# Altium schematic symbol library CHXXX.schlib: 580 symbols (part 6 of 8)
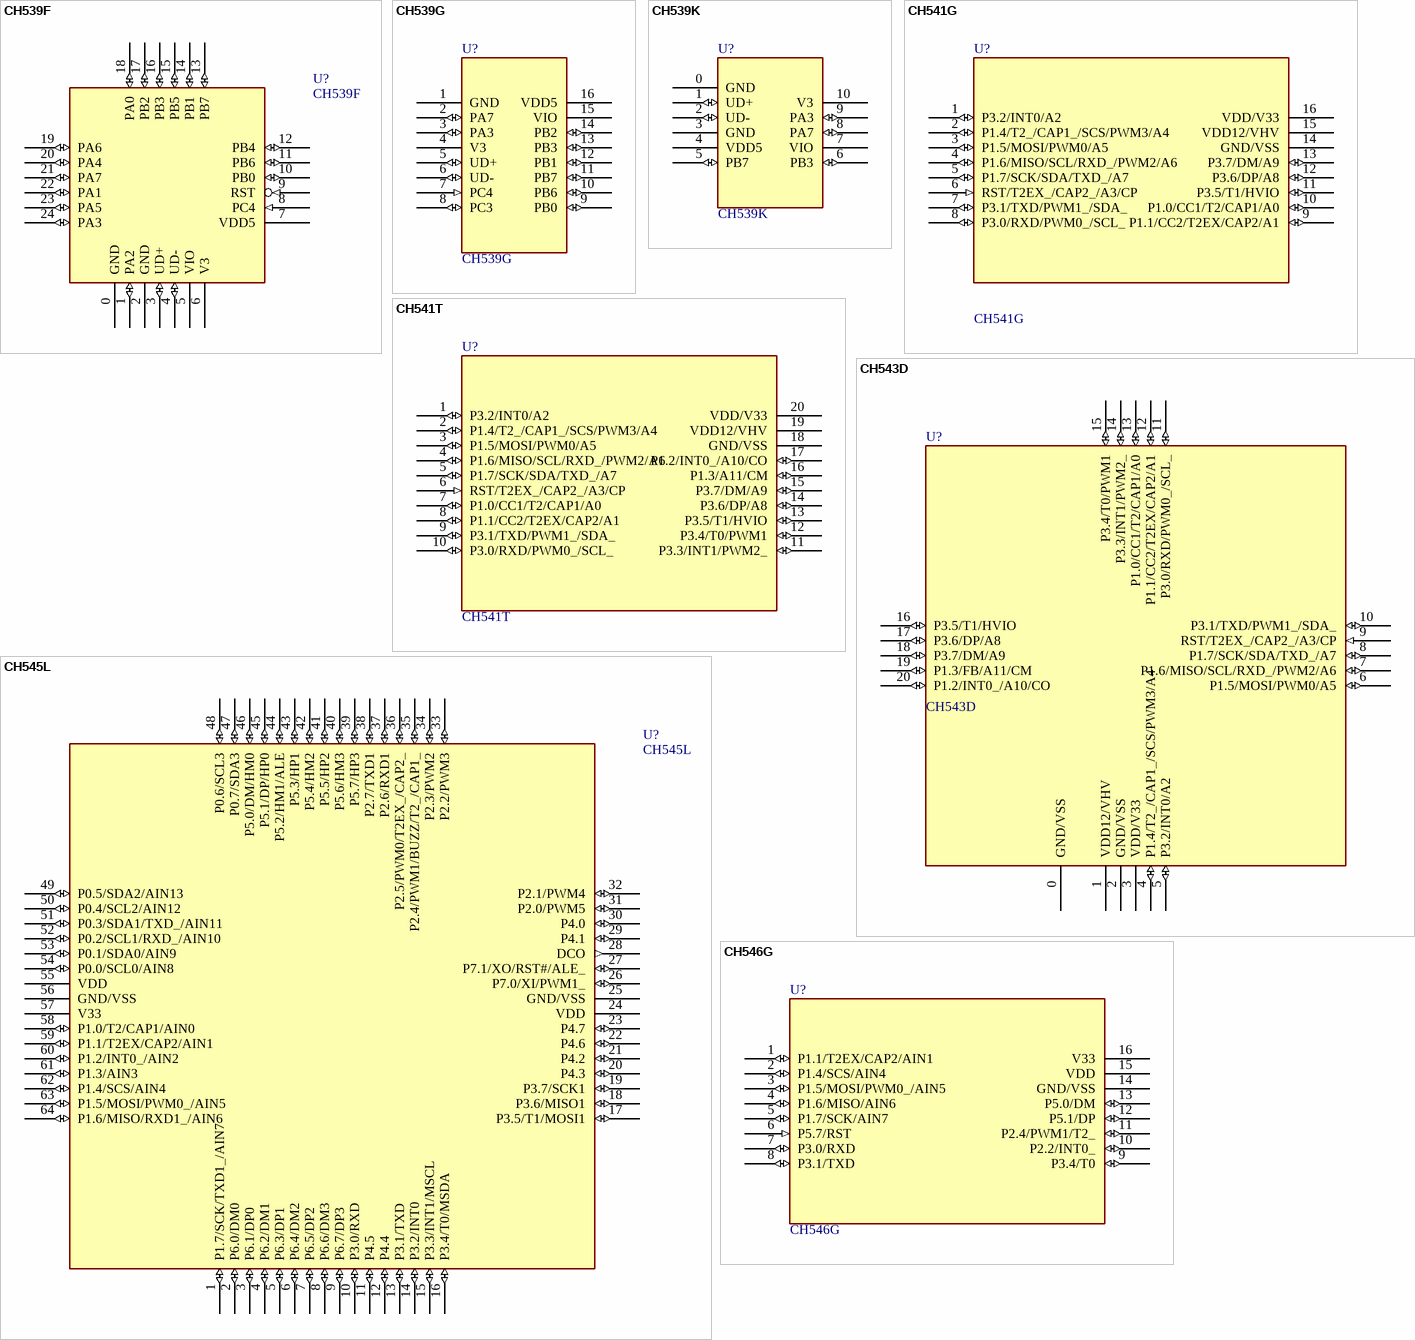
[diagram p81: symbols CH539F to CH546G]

## CH546G
designator U?
8bit MCS51 MCU with ADC & USB device & UART & SPI
footprint SOP16
footprint DIP16
pins: 1 P1.1/T2EX/CAP2/AIN1 (io), 2 P1.4/SCS/AIN4 (io), 3 P1.5/MOSI/PWM0_/AIN5 (io), 4 P1.6/MISO/AIN6 (io), 5 P1.7/SCK/AIN7 (io), 6 P5.7/RST (in), 7 P3.0/RXD (io), 8 P3.1/TXD (io), 9 P3.4/T0 (io), 10 P2.2/INT0_ (io), 11 P2.4/PWM1/T2_ (io), 12 P5.1/DP (io), 13 P5.0/DM (io), 14 GND/VSS (power), 15 VDD (power), 16 V33 (power)

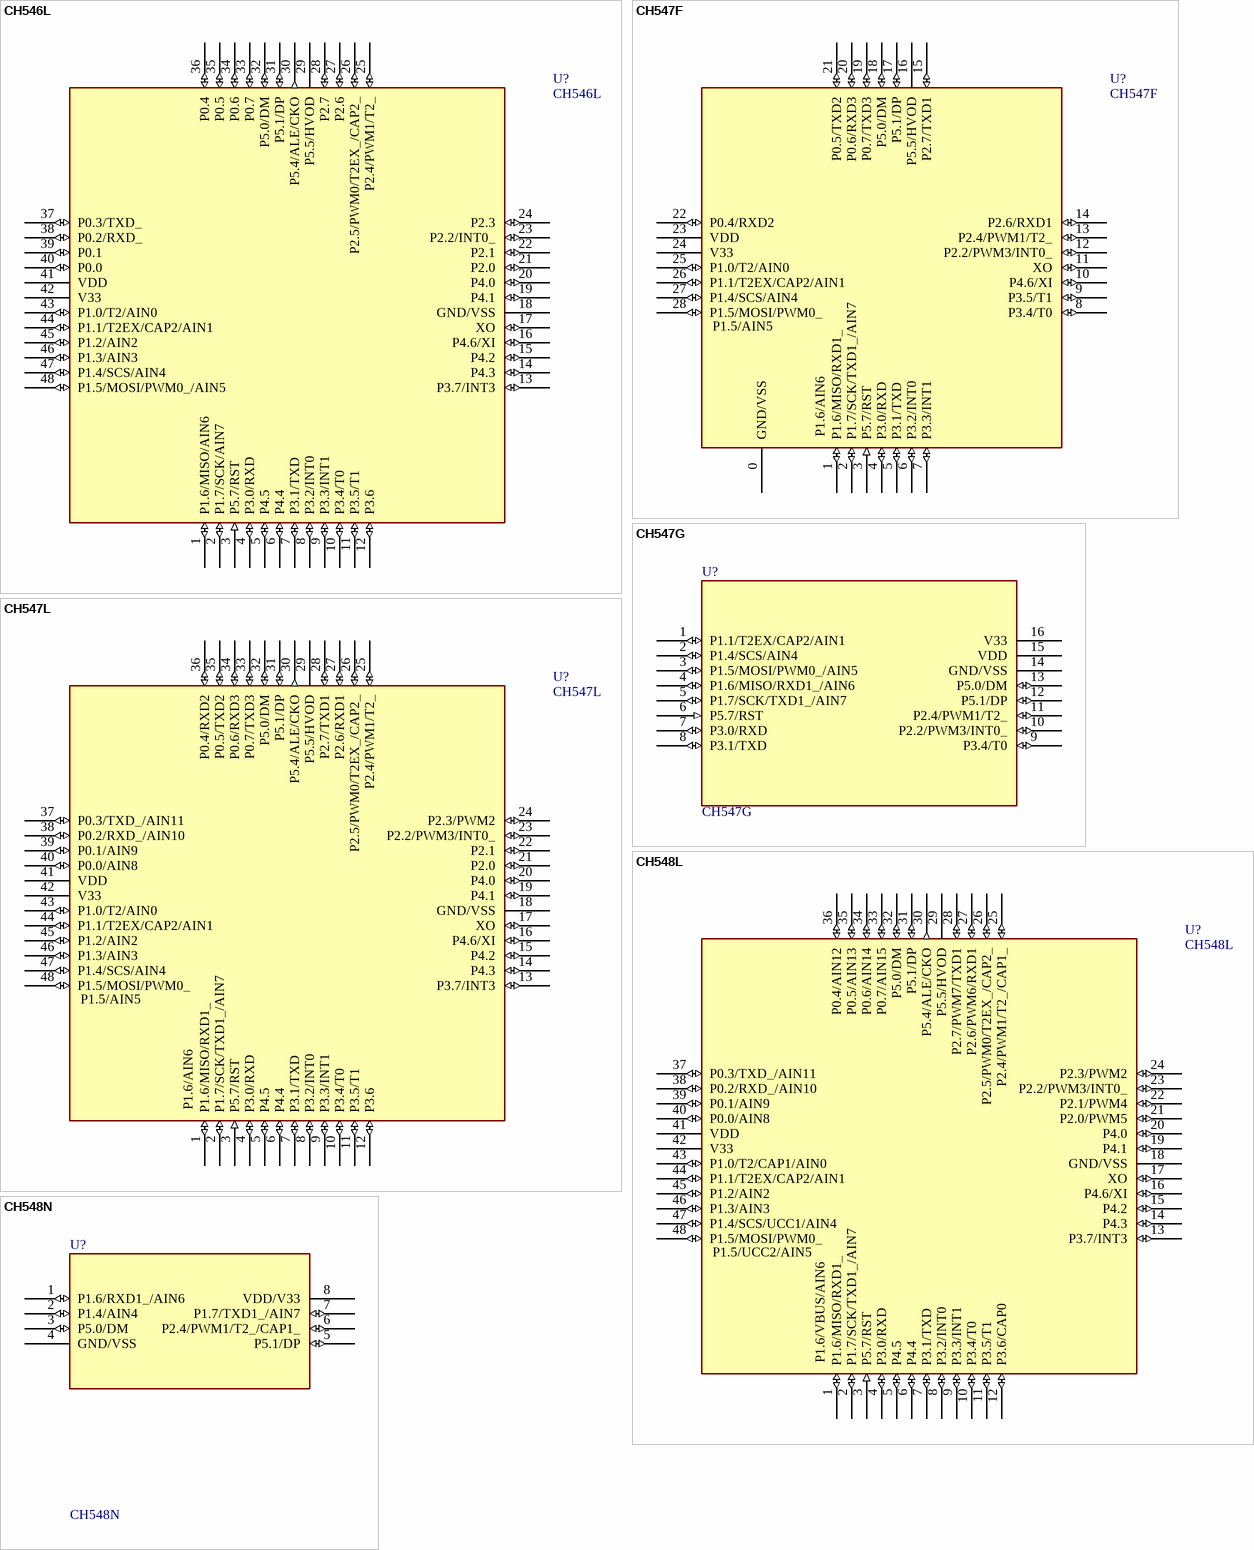
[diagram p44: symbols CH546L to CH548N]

## CH546L
designator U?
8bit MCS51 MCU with ADC & USB device & UART & SPI
footprint LQFP48
pins: 1 P1.6/MISO/AIN6 (io), 2 P1.7/SCK/AIN7 (io), 3 P5.7/RST (in), 4 P3.0/RXD (io), 5 P4.5 (io), 6 P4.4 (io), 7 P3.1/TXD (io), 8 P3.2/INT0 (io), 9 P3.3/INT1 (io), 10 P3.4/T0 (io), 11 P3.5/T1 (io), 12 P3.6 (io), 13 P3.7/INT3 (io), 14 P4.3 (io), 15 P4.2 (io), 16 P4.6/XI (io), 17 XO (io), 18 GND/VSS (power), 19 P4.1 (io), 20 P4.0 (io), 21 P2.0 (io), 22 P2.1 (io), 23 P2.2/INT0_ (io), 24 P2.3 (io), 25 P2.4/PWM1/T2_ (io), 26 P2.5/PWM0/T2EX_/CAP2_ (io), 27 P2.6 (io), 28 P2.7 (io), 29 P5.5/HVOD (oc), 30 P5.4/ALE/CKO (out), 31 P5.1/DP (io), 32 P5.0/DM (io), 33 P0.7 (io), 34 P0.6 (io), 35 P0.5 (io), 36 P0.4 (io), 37 P0.3/TXD_ (io), 38 P0.2/RXD_ (io), 39 P0.1 (io), 40 P0.0 (io), 41 VDD (power), 42 V33 (power), 43 P1.0/T2/AIN0 (io), 44 P1.1/T2EX/CAP2/AIN1 (io), 45 P1.2/AIN2 (io), 46 P1.3/AIN3 (io), 47 P1.4/SCS/AIN4 (io), 48 P1.5/MOSI/PWM0_/AIN5 (io)

## CH547F
designator U?
8bit MCS51 MCU with ADC & USB device & quad UART & SPI
footprint QFN28_4X4
pins: 0 GND/VSS (power), 1 P1.6/MISO/RXD1_ (io), 2 P1.7/SCK/TXD1_/AIN7 (io), 3 P5.7/RST (in), 4 P3.0/RXD (io), 5 P3.1/TXD (io), 6 P3.2/INT0 (io), 7 P3.3/INT1 (io), 8 P3.4/T0 (io), 9 P3.5/T1 (io), 10 P4.6/XI (io), 11 XO (io), 12 P2.2/PWM3/INT0_ (io), 13 P2.4/PWM1/T2_ (io), 14 P2.6/RXD1 (io), 15 P2.7/TXD1 (io), 16 P5.5/HVOD (oc), 17 P5.1/DP (io), 18 P5.0/DM (io), 19 P0.7/TXD3 (io), 20 P0.6/RXD3 (io), 21 P0.5/TXD2 (io), 22 P0.4/RXD2 (io), 23 VDD (power), 24 V33 (power), 25 P1.0/T2/AIN0 (io), 26 P1.1/T2EX/CAP2/AIN1 (io), 27 P1.4/SCS/AIN4 (io), 28 P1.5/MOSI/PWM0_ (io)

## CH547G
designator U?
8bit MCS51 MCU with ADC & USB device & dual UART & SPI
footprint SOP16
footprint DIP16
pins: 1 P1.1/T2EX/CAP2/AIN1 (io), 2 P1.4/SCS/AIN4 (io), 3 P1.5/MOSI/PWM0_/AIN5 (io), 4 P1.6/MISO/RXD1_/AIN6 (io), 5 P1.7/SCK/TXD1_/AIN7 (io), 6 P5.7/RST (in), 7 P3.0/RXD (io), 8 P3.1/TXD (io), 9 P3.4/T0 (io), 10 P2.2/PWM3/INT0_ (io), 11 P2.4/PWM1/T2_ (io), 12 P5.1/DP (io), 13 P5.0/DM (io), 14 GND/VSS (power), 15 VDD (power), 16 V33 (power)

## CH547L
designator U?
8bit MCS51 MCU with ADC & USB device & quad UART & SPI
footprint LQFP48
pins: 1 P1.6/MISO/RXD1_ (io), 2 P1.7/SCK/TXD1_/AIN7 (io), 3 P5.7/RST (in), 4 P3.0/RXD (io), 5 P4.5 (io), 6 P4.4 (io), 7 P3.1/TXD (io), 8 P3.2/INT0 (io), 9 P3.3/INT1 (io), 10 P3.4/T0 (io), 11 P3.5/T1 (io), 12 P3.6 (io), 13 P3.7/INT3 (io), 14 P4.3 (io), 15 P4.2 (io), 16 P4.6/XI (io), 17 XO (io), 18 GND/VSS (power), 19 P4.1 (io), 20 P4.0 (io), 21 P2.0 (io), 22 P2.1 (io), 23 P2.2/PWM3/INT0_ (io), 24 P2.3/PWM2 (io), 25 P2.4/PWM1/T2_ (io), 26 P2.5/PWM0/T2EX_/CAP2_ (io), 27 P2.6/RXD1 (io), 28 P2.7/TXD1 (io), 29 P5.5/HVOD (oc), 30 P5.4/ALE/CKO (out), 31 P5.1/DP (io), 32 P5.0/DM (io), 33 P0.7/TXD3 (io), 34 P0.6/RXD3 (io), 35 P0.5/TXD2 (io), 36 P0.4/RXD2 (io), 37 P0.3/TXD_/AIN11 (io), 38 P0.2/RXD_/AIN10 (io), 39 P0.1/AIN9 (io), 40 P0.0/AIN8 (io), 41 VDD (power), 42 V33 (power), 43 P1.0/T2/AIN0 (io), 44 P1.1/T2EX/CAP2/AIN1 (io), 45 P1.2/AIN2 (io), 46 P1.3/AIN3 (io), 47 P1.4/SCS/AIN4 (io), 48 P1.5/MOSI/PWM0_ (io)

## CH548L
designator U?
8bit MCS51 MCU with ADC & USB type-C host & device & double UART & SPI
footprint LQFP48
pins: 1 P1.6/MISO/RXD1_ (io), 2 P1.7/SCK/TXD1_/AIN7 (io), 3 P5.7/RST (in), 4 P3.0/RXD (io), 5 P4.5 (io), 6 P4.4 (io), 7 P3.1/TXD (io), 8 P3.2/INT0 (io), 9 P3.3/INT1 (io), 10 P3.4/T0 (io), 11 P3.5/T1 (io), 12 P3.6/CAP0 (io), 13 P3.7/INT3 (io), 14 P4.3 (io), 15 P4.2 (io), 16 P4.6/XI (io), 17 XO (io), 18 GND/VSS (power), 19 P4.1 (io), 20 P4.0 (io), 21 P2.0/PWM5 (io), 22 P2.1/PWM4 (io), 23 P2.2/PWM3/INT0_ (io), 24 P2.3/PWM2 (io), 25 P2.4/PWM1/T2_/CAP1_ (io), 26 P2.5/PWM0/T2EX_/CAP2_ (io), 27 P2.6/PWM6/RXD1 (io), 28 P2.7/PWM7/TXD1 (io), 29 P5.5/HVOD (oc), 30 P5.4/ALE/CKO (out), 31 P5.1/DP (io), 32 P5.0/DM (io), 33 P0.7/AIN15 (io), 34 P0.6/AIN14 (io), 35 P0.5/AIN13 (io), 36 P0.4/AIN12 (io), 37 P0.3/TXD_/AIN11 (io), 38 P0.2/RXD_/AIN10 (io), 39 P0.1/AIN9 (io), 40 P0.0/AIN8 (io), 41 VDD (power), 42 V33 (power), 43 P1.0/T2/CAP1/AIN0 (io), 44 P1.1/T2EX/CAP2/AIN1 (io), 45 P1.2/AIN2 (io), 46 P1.3/AIN3 (io), 47 P1.4/SCS/UCC1/AIN4 (io), 48 P1.5/MOSI/PWM0_ (io)

## CH548N
designator U?
8bit MCS51 MCU with ADC & USB host & device & UART
footprint SOP8 (Footprint not found)
pins: 1 P1.6/RXD1_/AIN6 (io), 2 P1.4/AIN4 (io), 3 P5.0/DM (io), 4 GND/VSS (power), 5 P5.1/DP (io), 6 P2.4/PWM1/T2_/CAP1_ (io), 7 P1.7/TXD1_/AIN7 (io), 8 VDD/V33 (power)

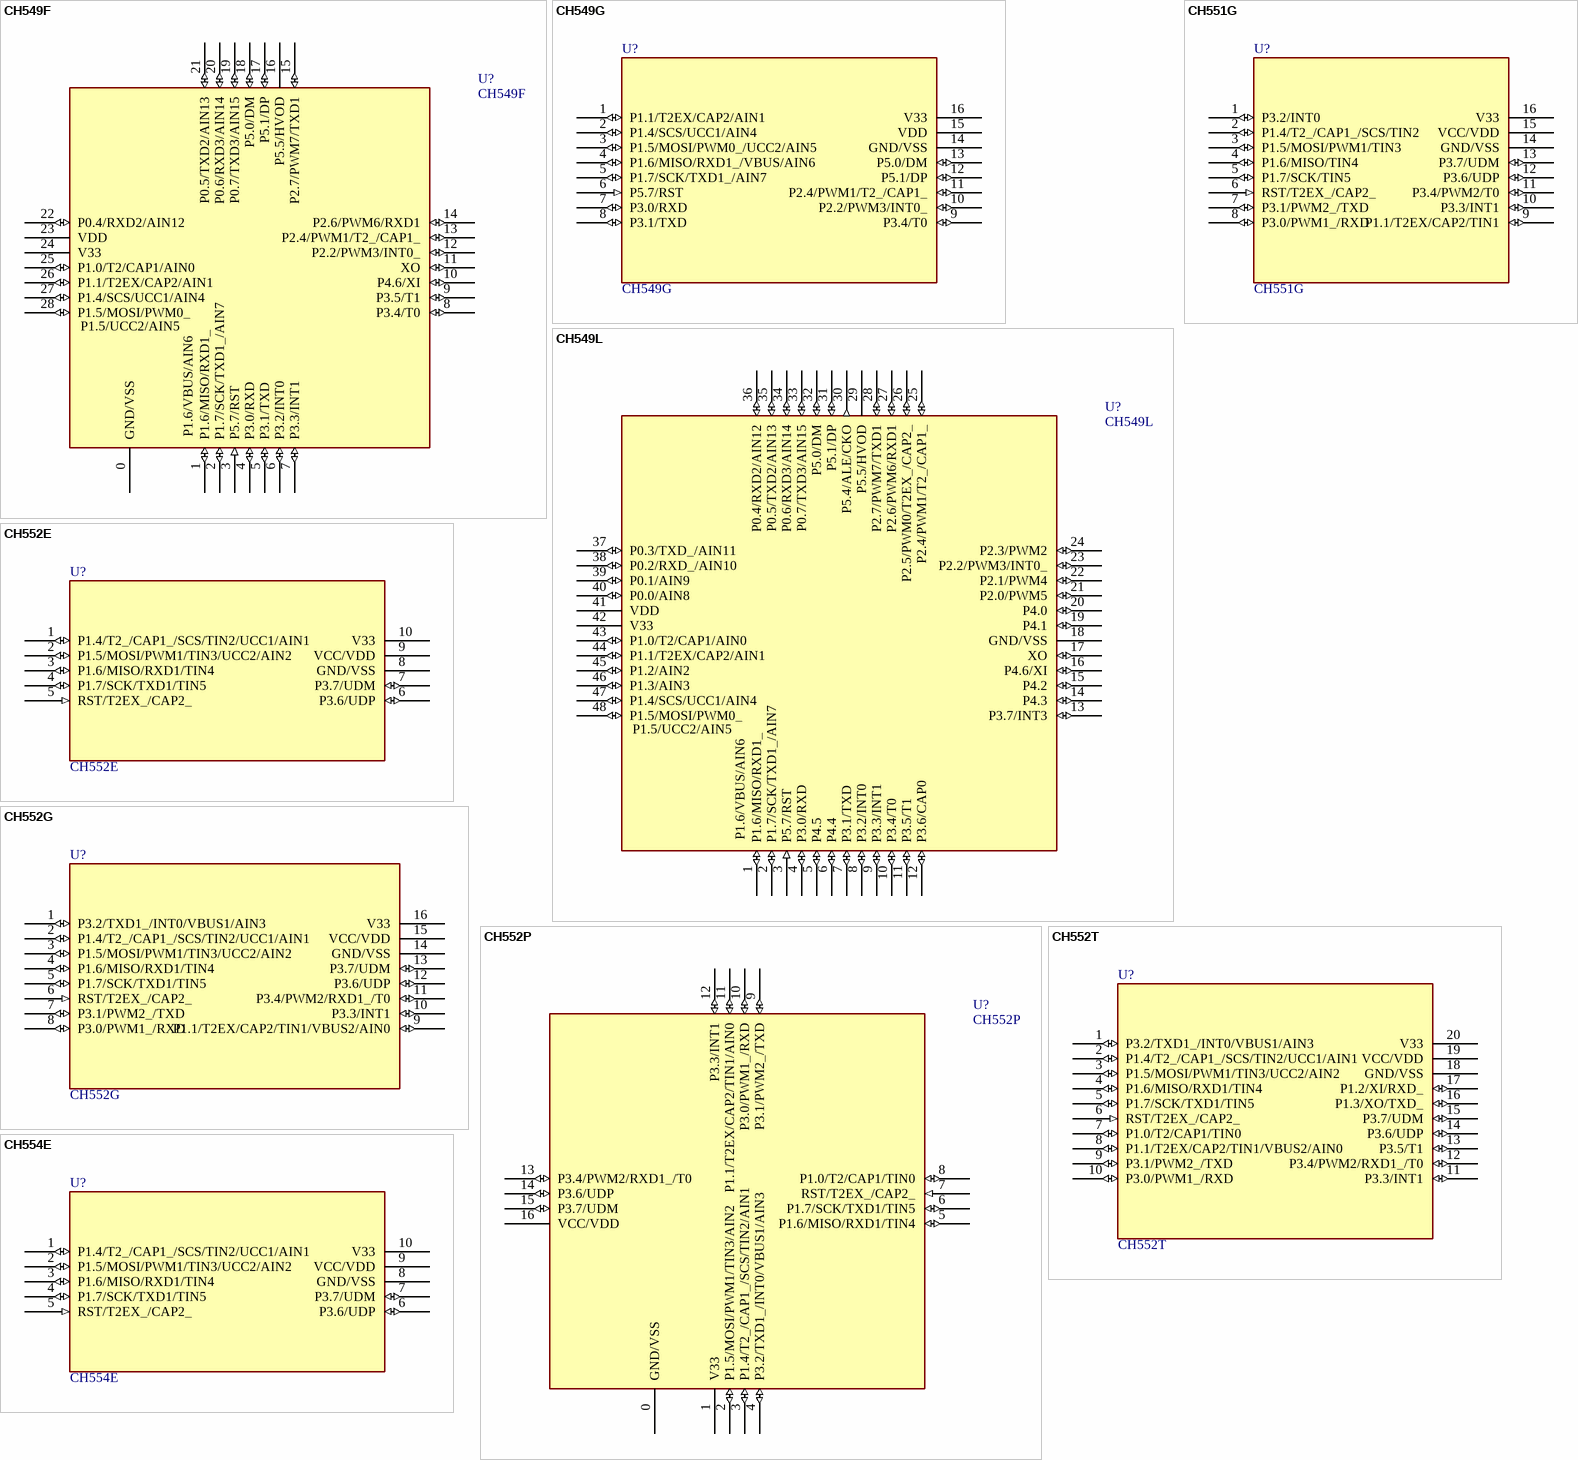
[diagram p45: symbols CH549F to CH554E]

## CH549F
designator U?
8bit MCS51 MCU with ADC & USB type-C host & device & quad UART & SPI
footprint QFN28_4X4
pins: 0 GND/VSS (power), 1 P1.6/MISO/RXD1_ (io), 2 P1.7/SCK/TXD1_/AIN7 (io), 3 P5.7/RST (in), 4 P3.0/RXD (io), 5 P3.1/TXD (io), 6 P3.2/INT0 (io), 7 P3.3/INT1 (io), 8 P3.4/T0 (io), 9 P3.5/T1 (io), 10 P4.6/XI (io), 11 XO (io), 12 P2.2/PWM3/INT0_ (io), 13 P2.4/PWM1/T2_/CAP1_ (io), 14 P2.6/PWM6/RXD1 (io), 15 P2.7/PWM7/TXD1 (io), 16 P5.5/HVOD (oc), 17 P5.1/DP (io), 18 P5.0/DM (io), 19 P0.7/TXD3/AIN15 (io), 20 P0.6/RXD3/AIN14 (io), 21 P0.5/TXD2/AIN13 (io), 22 P0.4/RXD2/AIN12 (io), 23 VDD (power), 24 V33 (power), 25 P1.0/T2/CAP1/AIN0 (io), 26 P1.1/T2EX/CAP2/AIN1 (io), 27 P1.4/SCS/UCC1/AIN4 (io), 28 P1.5/MOSI/PWM0_ (io)

## CH549G
designator U?
8bit MCS51 MCU with ADC & USB type-C host & device & dual UART & SPI
footprint SOP16
footprint DIP16
pins: 1 P1.1/T2EX/CAP2/AIN1 (io), 2 P1.4/SCS/UCC1/AIN4 (io), 3 P1.5/MOSI/PWM0_/UCC2/AIN5 (io), 4 P1.6/MISO/RXD1_/VBUS/AIN6 (io), 5 P1.7/SCK/TXD1_/AIN7 (io), 6 P5.7/RST (in), 7 P3.0/RXD (io), 8 P3.1/TXD (io), 9 P3.4/T0 (io), 10 P2.2/PWM3/INT0_ (io), 11 P2.4/PWM1/T2_/CAP1_ (io), 12 P5.1/DP (io), 13 P5.0/DM (io), 14 GND/VSS (power), 15 VDD (power), 16 V33 (power)

## CH549L
designator U?
8bit MCS51 MCU with ADC & USB type-C host & device & quad UART & SPI
footprint LQFP48
pins: 1 P1.6/MISO/RXD1_ (io), 2 P1.7/SCK/TXD1_/AIN7 (io), 3 P5.7/RST (in), 4 P3.0/RXD (io), 5 P4.5 (io), 6 P4.4 (io), 7 P3.1/TXD (io), 8 P3.2/INT0 (io), 9 P3.3/INT1 (io), 10 P3.4/T0 (io), 11 P3.5/T1 (io), 12 P3.6/CAP0 (io), 13 P3.7/INT3 (io), 14 P4.3 (io), 15 P4.2 (io), 16 P4.6/XI (io), 17 XO (io), 18 GND/VSS (power), 19 P4.1 (io), 20 P4.0 (io), 21 P2.0/PWM5 (io), 22 P2.1/PWM4 (io), 23 P2.2/PWM3/INT0_ (io), 24 P2.3/PWM2 (io), 25 P2.4/PWM1/T2_/CAP1_ (io), 26 P2.5/PWM0/T2EX_/CAP2_ (io), 27 P2.6/PWM6/RXD1 (io), 28 P2.7/PWM7/TXD1 (io), 29 P5.5/HVOD (oc), 30 P5.4/ALE/CKO (out), 31 P5.1/DP (io), 32 P5.0/DM (io), 33 P0.7/TXD3/AIN15 (io), 34 P0.6/RXD3/AIN14 (io), 35 P0.5/TXD2/AIN13 (io), 36 P0.4/RXD2/AIN12 (io), 37 P0.3/TXD_/AIN11 (io), 38 P0.2/RXD_/AIN10 (io), 39 P0.1/AIN9 (io), 40 P0.0/AIN8 (io), 41 VDD (power), 42 V33 (power), 43 P1.0/T2/CAP1/AIN0 (io), 44 P1.1/T2EX/CAP2/AIN1 (io), 45 P1.2/AIN2 (io), 46 P1.3/AIN3 (io), 47 P1.4/SCS/UCC1/AIN4 (io), 48 P1.5/MOSI/PWM0_ (io)

## CH551G
designator U?
8bit MCS51 MCU with SPI & UART & USB device
footprint SOP16
footprint DIP16
pins: 1 P3.2/INT0 (io), 2 P1.4/T2_/CAP1_/SCS/TIN2 (io), 3 P1.5/MOSI/PWM1/TIN3 (io), 4 P1.6/MISO/TIN4 (io), 5 P1.7/SCK/TIN5 (io), 6 RST/T2EX_/CAP2_ (in), 7 P3.1/PWM2_/TXD (io), 8 P3.0/PWM1_/RXD (io), 9 P1.1/T2EX/CAP2/TIN1 (io), 10 P3.3/INT1 (io), 11 P3.4/PWM2/T0 (io), 12 P3.6/UDP (io), 13 P3.7/UDM (io), 14 GND/VSS (power), 15 VCC/VDD (power), 16 V33 (power)

## CH552E
designator U?
8bit MCS51 MCU with ADC & SPI & USB device & dual UART
footprint MSOP10
pins: 1 P1.4/T2_/CAP1_/SCS/TIN2/UCC1/AIN1 (io), 2 P1.5/MOSI/PWM1/TIN3/UCC2/AIN2 (io), 3 P1.6/MISO/RXD1/TIN4 (io), 4 P1.7/SCK/TXD1/TIN5 (io), 5 RST/T2EX_/CAP2_ (in), 6 P3.6/UDP (io), 7 P3.7/UDM (io), 8 GND/VSS (power), 9 VCC/VDD (power), 10 V33 (power)

## CH552G
designator U?
8bit MCS51 MCU with ADC & SPI & USB device & dual UART
footprint SOP16
footprint DIP16
pins: 1 P3.2/TXD1_/INT0/VBUS1/AIN3 (io), 2 P1.4/T2_/CAP1_/SCS/TIN2/UCC1/AIN1 (io), 3 P1.5/MOSI/PWM1/TIN3/UCC2/AIN2 (io), 4 P1.6/MISO/RXD1/TIN4 (io), 5 P1.7/SCK/TXD1/TIN5 (io), 6 RST/T2EX_/CAP2_ (in), 7 P3.1/PWM2_/TXD (io), 8 P3.0/PWM1_/RXD (io), 9 P1.1/T2EX/CAP2/TIN1/VBUS2/AIN0 (io), 10 P3.3/INT1 (io), 11 P3.4/PWM2/RXD1_/T0 (io), 12 P3.6/UDP (io), 13 P3.7/UDM (io), 14 GND/VSS (power), 15 VCC/VDD (power), 16 V33 (power)

## CH552P
designator U?
8bit MCS51 MCU with ADC & SPI & USB device & dual UART
footprint QFN16_3X3
pins: 0 GND/VSS (power), 1 V33 (power), 2 P1.5/MOSI/PWM1/TIN3/AIN2 (io), 3 P1.4/T2_/CAP1_/SCS/TIN2/AIN1 (io), 4 P3.2/TXD1_/INT0/VBUS1/AIN3 (io), 5 P1.6/MISO/RXD1/TIN4 (io), 6 P1.7/SCK/TXD1/TIN5 (io), 7 RST/T2EX_/CAP2_ (in), 8 P1.0/T2/CAP1/TIN0 (io), 9 P3.1/PWM2_/TXD (io), 10 P3.0/PWM1_/RXD (io), 11 P1.1/T2EX/CAP2/TIN1/AIN0 (io), 12 P3.3/INT1 (io), 13 P3.4/PWM2/RXD1_/T0 (io), 14 P3.6/UDP (io), 15 P3.7/UDM (io), 16 VCC/VDD (power)

## CH552T
designator U?
8bit MCS51 MCU with ADC & SPI & USB device & dual UART
footprint TSSOP20
footprint DIP20
pins: 1 P3.2/TXD1_/INT0/VBUS1/AIN3 (io), 2 P1.4/T2_/CAP1_/SCS/TIN2/UCC1/AIN1 (io), 3 P1.5/MOSI/PWM1/TIN3/UCC2/AIN2 (io), 4 P1.6/MISO/RXD1/TIN4 (io), 5 P1.7/SCK/TXD1/TIN5 (io), 6 RST/T2EX_/CAP2_ (in), 7 P1.0/T2/CAP1/TIN0 (io), 8 P1.1/T2EX/CAP2/TIN1/VBUS2/AIN0 (io), 9 P3.1/PWM2_/TXD (io), 10 P3.0/PWM1_/RXD (io), 11 P3.3/INT1 (io), 12 P3.4/PWM2/RXD1_/T0 (io), 13 P3.5/T1 (io), 14 P3.6/UDP (io), 15 P3.7/UDM (io), 16 P1.3/XO/TXD_ (io), 17 P1.2/XI/RXD_ (io), 18 GND/VSS (power), 19 VCC/VDD (power), 20 V33 (power)

## CH554E
designator U?
8bit MCS51 MCU with ADC & SPI & USB host & device & dual UART
footprint MSOP10
pins: 1 P1.4/T2_/CAP1_/SCS/TIN2/UCC1/AIN1 (io), 2 P1.5/MOSI/PWM1/TIN3/UCC2/AIN2 (io), 3 P1.6/MISO/RXD1/TIN4 (io), 4 P1.7/SCK/TXD1/TIN5 (io), 5 RST/T2EX_/CAP2_ (in), 6 P3.6/UDP (io), 7 P3.7/UDM (io), 8 GND/VSS (power), 9 VCC/VDD (power), 10 V33 (power)

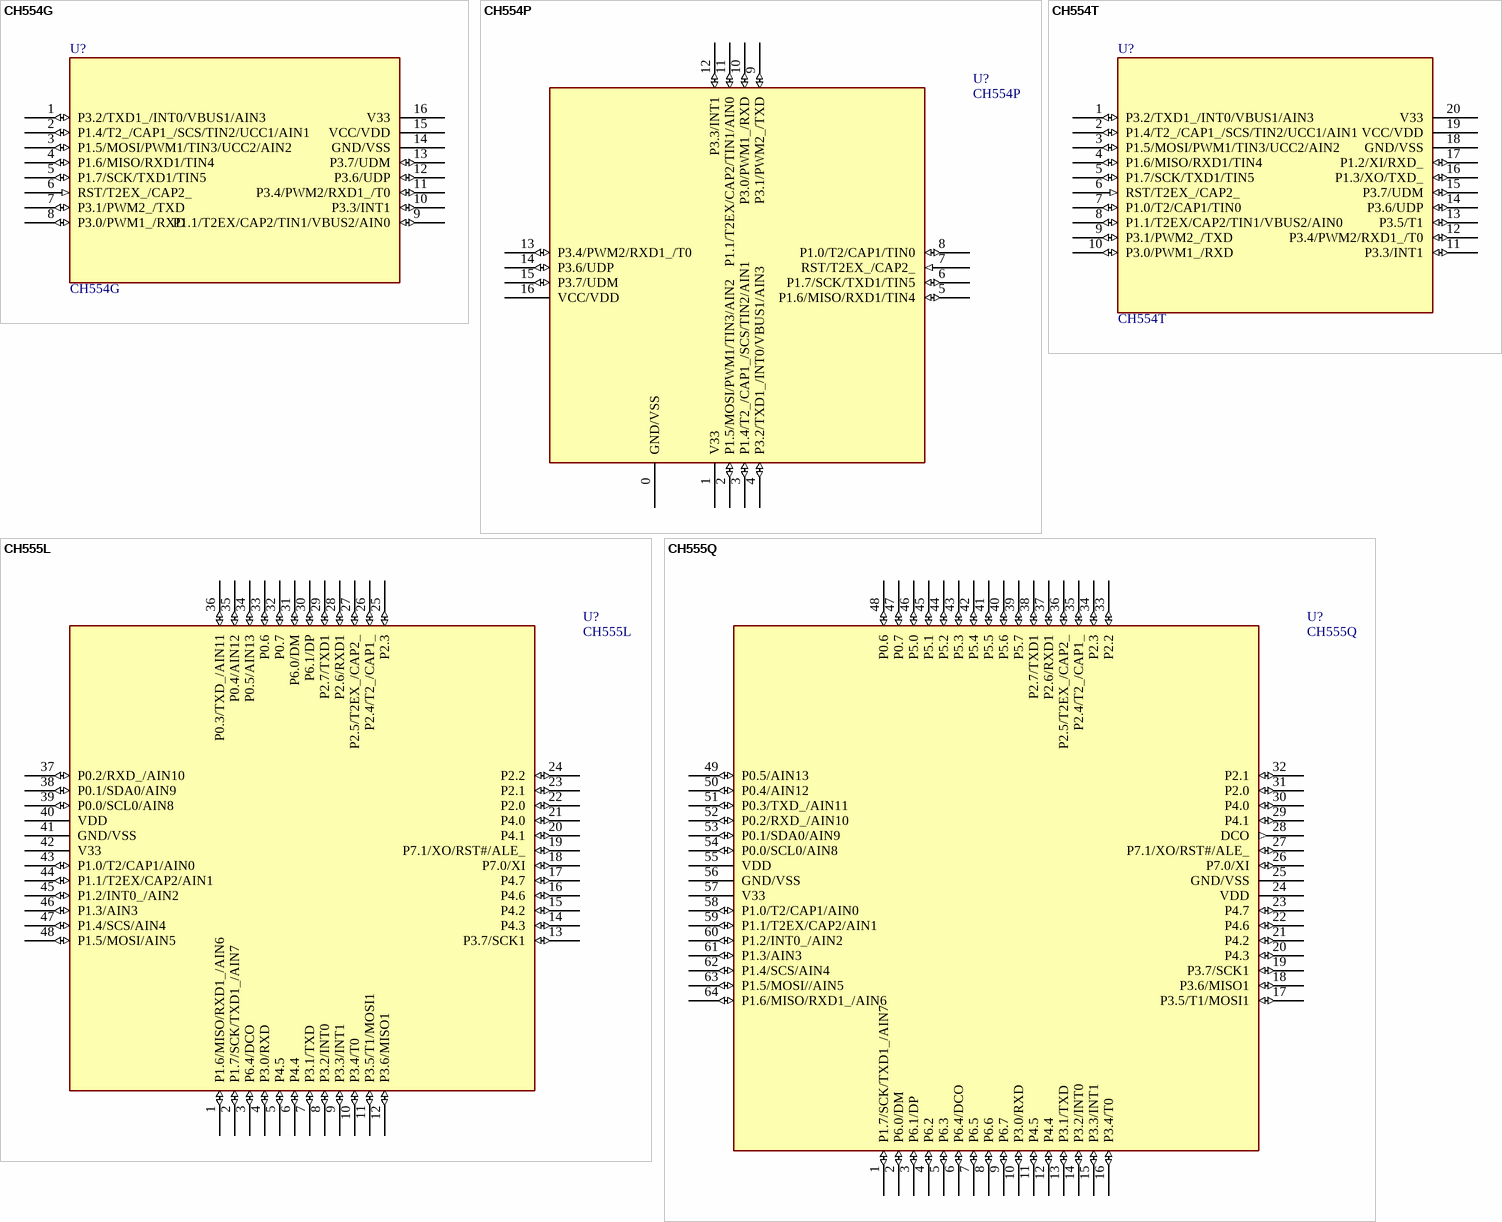
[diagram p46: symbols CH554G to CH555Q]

## CH554G
designator U?
8bit MCS51 MCU with ADC & SPI & USB host & device & dual UART
footprint SOP16
footprint DIP16
pins: 1 P3.2/TXD1_/INT0/VBUS1/AIN3 (io), 2 P1.4/T2_/CAP1_/SCS/TIN2/UCC1/AIN1 (io), 3 P1.5/MOSI/PWM1/TIN3/UCC2/AIN2 (io), 4 P1.6/MISO/RXD1/TIN4 (io), 5 P1.7/SCK/TXD1/TIN5 (io), 6 RST/T2EX_/CAP2_ (in), 7 P3.1/PWM2_/TXD (io), 8 P3.0/PWM1_/RXD (io), 9 P1.1/T2EX/CAP2/TIN1/VBUS2/AIN0 (io), 10 P3.3/INT1 (io), 11 P3.4/PWM2/RXD1_/T0 (io), 12 P3.6/UDP (io), 13 P3.7/UDM (io), 14 GND/VSS (power), 15 VCC/VDD (power), 16 V33 (power)

## CH554P
designator U?
8bit MCS51 MCU with ADC & SPI & USB host & device & dual UART
footprint QFN16_3X3
pins: 0 GND/VSS (power), 1 V33 (power), 2 P1.5/MOSI/PWM1/TIN3/AIN2 (io), 3 P1.4/T2_/CAP1_/SCS/TIN2/AIN1 (io), 4 P3.2/TXD1_/INT0/VBUS1/AIN3 (io), 5 P1.6/MISO/RXD1/TIN4 (io), 6 P1.7/SCK/TXD1/TIN5 (io), 7 RST/T2EX_/CAP2_ (in), 8 P1.0/T2/CAP1/TIN0 (io), 9 P3.1/PWM2_/TXD (io), 10 P3.0/PWM1_/RXD (io), 11 P1.1/T2EX/CAP2/TIN1/AIN0 (io), 12 P3.3/INT1 (io), 13 P3.4/PWM2/RXD1_/T0 (io), 14 P3.6/UDP (io), 15 P3.7/UDM (io), 16 VCC/VDD (power)

## CH554T
designator U?
8bit MCS51 MCU with ADC & SPI & USB host & device & dual UART
footprint TSSOP20
footprint DIP20
pins: 1 P3.2/TXD1_/INT0/VBUS1/AIN3 (io), 2 P1.4/T2_/CAP1_/SCS/TIN2/UCC1/AIN1 (io), 3 P1.5/MOSI/PWM1/TIN3/UCC2/AIN2 (io), 4 P1.6/MISO/RXD1/TIN4 (io), 5 P1.7/SCK/TXD1/TIN5 (io), 6 RST/T2EX_/CAP2_ (in), 7 P1.0/T2/CAP1/TIN0 (io), 8 P1.1/T2EX/CAP2/TIN1/VBUS2/AIN0 (io), 9 P3.1/PWM2_/TXD (io), 10 P3.0/PWM1_/RXD (io), 11 P3.3/INT1 (io), 12 P3.4/PWM2/RXD1_/T0 (io), 13 P3.5/T1 (io), 14 P3.6/UDP (io), 15 P3.7/UDM (io), 16 P1.3/XO/TXD_ (io), 17 P1.2/XI/RXD_ (io), 18 GND/VSS (power), 19 VCC/VDD (power), 20 V33 (power)

## CH555L
designator U?
8bit MCS51 MCU with ADC & USB device & RGB PWM & UART & SPI & I2C
footprint LQFP48
pins: 1 P1.6/MISO/RXD1_/AIN6 (io), 2 P1.7/SCK/TXD1_/AIN7 (io), 3 P6.4/DCO (io), 4 P3.0/RXD (io), 5 P4.5 (io), 6 P4.4 (io), 7 P3.1/TXD (io), 8 P3.2/INT0 (io), 9 P3.3/INT1 (io), 10 P3.4/T0 (io), 11 P3.5/T1/MOSI1 (io), 12 P3.6/MISO1 (io), 13 P3.7/SCK1 (io), 14 P4.3 (io), 15 P4.2 (io), 16 P4.6 (io), 17 P4.7 (io), 18 P7.0/XI (io), 19 P7.1/XO/RST#/ALE_ (io), 20 P4.1 (io), 21 P4.0 (io), 22 P2.0 (io), 23 P2.1 (io), 24 P2.2 (io), 25 P2.3 (io), 26 P2.4/T2_/CAP1_ (io), 27 P2.5/T2EX_/CAP2_ (io), 28 P2.6/RXD1 (io), 29 P2.7/TXD1 (io), 30 P6.1/DP (io), 31 P6.0/DM (io), 32 P0.7 (io), 33 P0.6 (io), 34 P0.5/AIN13 (io), 35 P0.4/AIN12 (io), 36 P0.3/TXD_/AIN11 (io), 37 P0.2/RXD_/AIN10 (io), 38 P0.1/SDA0/AIN9 (io), 39 P0.0/SCL0/AIN8 (io), 40 VDD (power), 41 GND/VSS (power), 42 V33 (power), 43 P1.0/T2/CAP1/AIN0 (io), 44 P1.1/T2EX/CAP2/AIN1 (io), 45 P1.2/INT0_/AIN2 (io), 46 P1.3/AIN3 (io), 47 P1.4/SCS/AIN4 (io), 48 P1.5/MOSI/AIN5 (io)

## CH555Q
designator U?
8bit MCS51 MCU with ADC & USB device & RGB PWM & UART & SPI & I2C
footprint LQFP64
pins: 1 P1.7/SCK/TXD1_/AIN7 (io), 2 P6.0/DM (io), 3 P6.1/DP (io), 4 P6.2 (io), 5 P6.3 (io), 6 P6.4/DCO (io), 7 P6.5 (io), 8 P6.6 (io), 9 P6.7 (io), 10 P3.0/RXD (io), 11 P4.5 (io), 12 P4.4 (io), 13 P3.1/TXD (io), 14 P3.2/INT0 (io), 15 P3.3/INT1 (io), 16 P3.4/T0 (io), 17 P3.5/T1/MOSI1 (io), 18 P3.6/MISO1 (io), 19 P3.7/SCK1 (io), 20 P4.3 (io), 21 P4.2 (io), 22 P4.6 (io), 23 P4.7 (io), 24 VDD (power), 25 GND/VSS (power), 26 P7.0/XI (io), 27 P7.1/XO/RST#/ALE_ (io), 28 DCO (out), 29 P4.1 (io), 30 P4.0 (io), 31 P2.0 (io), 32 P2.1 (io), 33 P2.2 (io), 34 P2.3 (io), 35 P2.4/T2_/CAP1_ (io), 36 P2.5/T2EX_/CAP2_ (io), 37 P2.6/RXD1 (io), 38 P2.7/TXD1 (io), 39 P5.7 (io), 40 P5.6 (io), 41 P5.5 (io), 42 P5.4 (io), 43 P5.3 (io), 44 P5.2 (io), 45 P5.1 (io), 46 P5.0 (io), 47 P0.7 (io), 48 P0.6 (io), 49 P0.5/AIN13 (io), 50 P0.4/AIN12 (io), 51 P0.3/TXD_/AIN11 (io), 52 P0.2/RXD_/AIN10 (io), 53 P0.1/SDA0/AIN9 (io), 54 P0.0/SCL0/AIN8 (io), 55 VDD (power), 56 GND/VSS (power), 57 V33 (power), 58 P1.0/T2/CAP1/AIN0 (io), 59 P1.1/T2EX/CAP2/AIN1 (io), 60 P1.2/INT0_/AIN2 (io), 61 P1.3/AIN3 (io), 62 P1.4/SCS/AIN4 (io), 63 P1.5/MOSI//AIN5 (io), 64 P1.6/MISO/RXD1_/AIN6 (io)

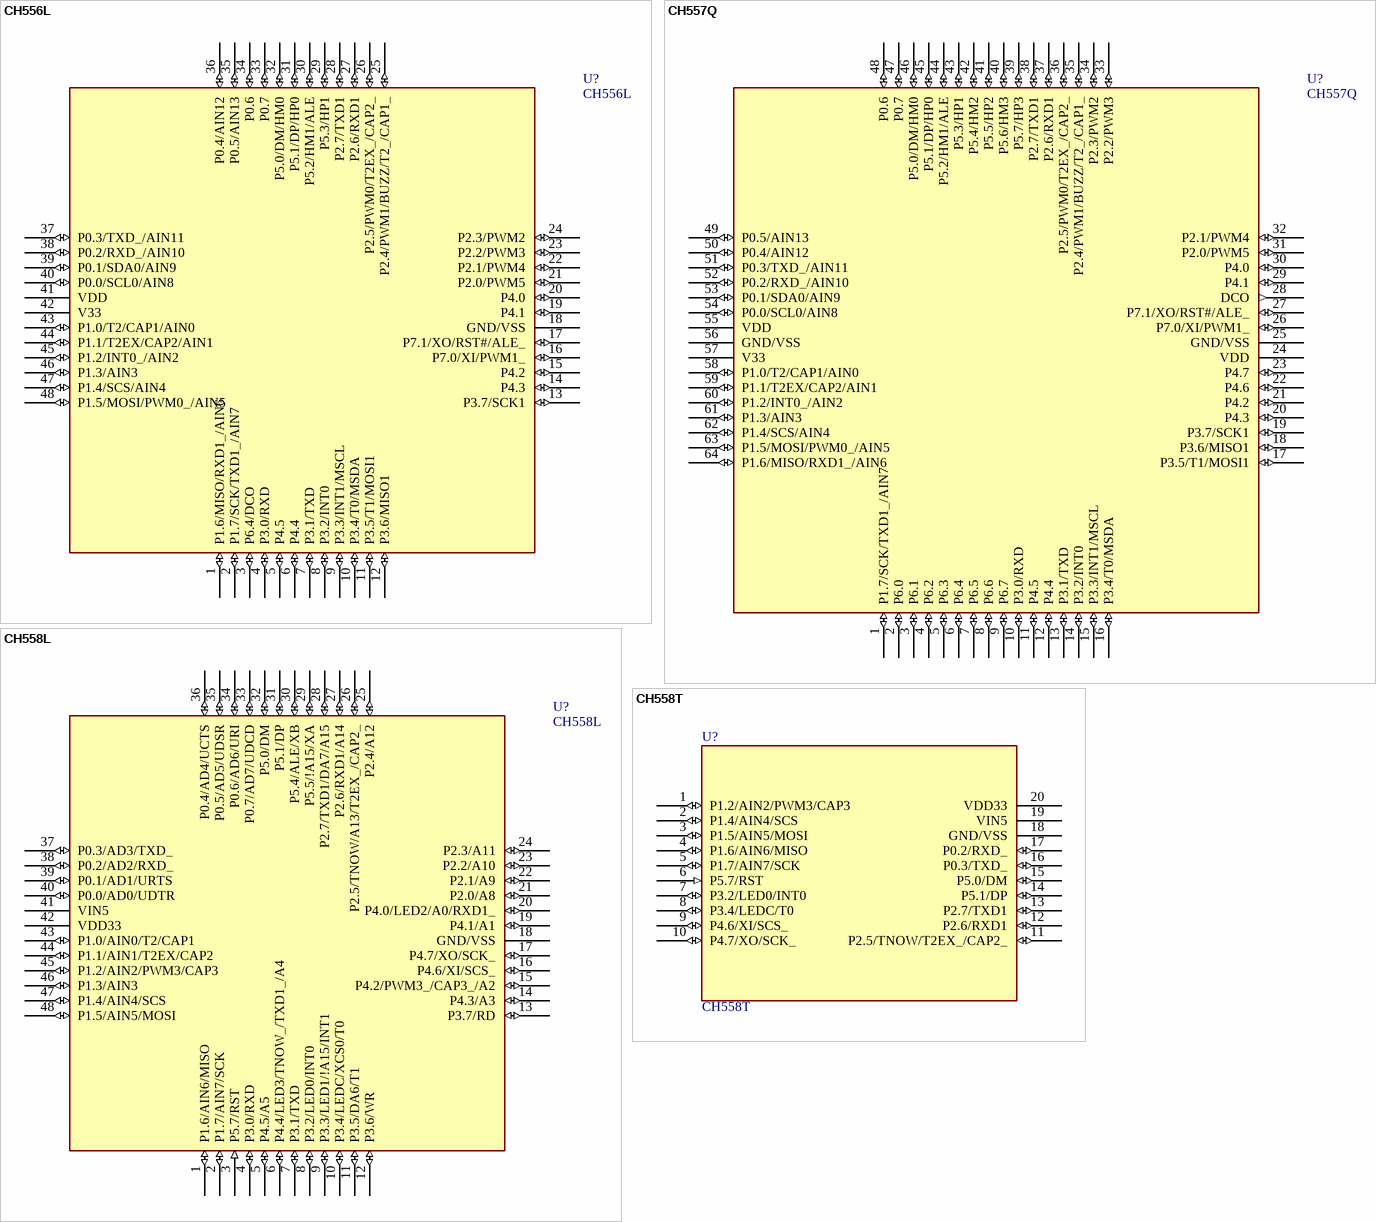
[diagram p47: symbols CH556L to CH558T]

## CH556L
designator U?
8bit MCS51 MCU with ADC & USB host 2 ports & device & dual UART & SPI & I2C
footprint LQFP48
pins: 1 P1.6/MISO/RXD1_/AIN6 (io), 2 P1.7/SCK/TXD1_/AIN7 (io), 3 P6.4/DCO (io), 4 P3.0/RXD (io), 5 P4.5 (io), 6 P4.4 (io), 7 P3.1/TXD (io), 8 P3.2/INT0 (io), 9 P3.3/INT1/MSCL (io), 10 P3.4/T0/MSDA (io), 11 P3.5/T1/MOSI1 (io), 12 P3.6/MISO1 (io), 13 P3.7/SCK1 (io), 14 P4.3 (io), 15 P4.2 (io), 16 P7.0/XI/PWM1_ (io), 17 P7.1/XO/RST#/ALE_ (io), 18 GND/VSS (power), 19 P4.1 (io), 20 P4.0 (io), 21 P2.0/PWM5 (io), 22 P2.1/PWM4 (io), 23 P2.2/PWM3 (io), 24 P2.3/PWM2 (io), 25 P2.4/PWM1/BUZZ/T2_/CAP1_ (io), 26 P2.5/PWM0/T2EX_/CAP2_ (io), 27 P2.6/RXD1 (io), 28 P2.7/TXD1 (io), 29 P5.3/HP1 (io), 30 P5.2/HM1/ALE (io), 31 P5.1/DP/HP0 (io), 32 P5.0/DM/HM0 (io), 33 P0.7 (io), 34 P0.6 (io), 35 P0.5/AIN13 (io), 36 P0.4/AIN12 (io), 37 P0.3/TXD_/AIN11 (io), 38 P0.2/RXD_/AIN10 (io), 39 P0.1/SDA0/AIN9 (io), 40 P0.0/SCL0/AIN8 (io), 41 VDD (power), 42 V33 (power), 43 P1.0/T2/CAP1/AIN0 (io), 44 P1.1/T2EX/CAP2/AIN1 (io), 45 P1.2/INT0_/AIN2 (io), 46 P1.3/AIN3 (io), 47 P1.4/SCS/AIN4 (io), 48 P1.5/MOSI/PWM0_/AIN5 (io)

## CH557Q
designator U?
8bit MCS51 MCU with ADC & USB host 4 ports & USB device & RGB PWM & dual UART & SPI & I2C
footprint LQFP64
pins: 1 P1.7/SCK/TXD1_/AIN7 (io), 2 P6.0 (io), 3 P6.1 (io), 4 P6.2 (io), 5 P6.3 (io), 6 P6.4 (io), 7 P6.5 (io), 8 P6.6 (io), 9 P6.7 (io), 10 P3.0/RXD (io), 11 P4.5 (io), 12 P4.4 (io), 13 P3.1/TXD (io), 14 P3.2/INT0 (io), 15 P3.3/INT1/MSCL (io), 16 P3.4/T0/MSDA (io), 17 P3.5/T1/MOSI1 (io), 18 P3.6/MISO1 (io), 19 P3.7/SCK1 (io), 20 P4.3 (io), 21 P4.2 (io), 22 P4.6 (io), 23 P4.7 (io), 24 VDD (power), 25 GND/VSS (power), 26 P7.0/XI/PWM1_ (io), 27 P7.1/XO/RST#/ALE_ (io), 28 DCO (out), 29 P4.1 (io), 30 P4.0 (io), 31 P2.0/PWM5 (io), 32 P2.1/PWM4 (io), 33 P2.2/PWM3 (io), 34 P2.3/PWM2 (io), 35 P2.4/PWM1/BUZZ/T2_/CAP1_ (io), 36 P2.5/PWM0/T2EX_/CAP2_ (io), 37 P2.6/RXD1 (io), 38 P2.7/TXD1 (io), 39 P5.7/HP3 (io), 40 P5.6/HM3 (io), 41 P5.5/HP2 (io), 42 P5.4/HM2 (io), 43 P5.3/HP1 (io), 44 P5.2/HM1/ALE (io), 45 P5.1/DP/HP0 (io), 46 P5.0/DM/HM0 (io), 47 P0.7 (io), 48 P0.6 (io), 49 P0.5/AIN13 (io), 50 P0.4/AIN12 (io), 51 P0.3/TXD_/AIN11 (io), 52 P0.2/RXD_/AIN10 (io), 53 P0.1/SDA0/AIN9 (io), 54 P0.0/SCL0/AIN8 (io), 55 VDD (power), 56 GND/VSS (power), 57 V33 (power), 58 P1.0/T2/CAP1/AIN0 (io), 59 P1.1/T2EX/CAP2/AIN1 (io), 60 P1.2/INT0_/AIN2 (io), 61 P1.3/AIN3 (io), 62 P1.4/SCS/AIN4 (io), 63 P1.5/MOSI/PWM0_/AIN5 (io), 64 P1.6/MISO/RXD1_/AIN6 (io)

## CH558L
designator U?
8bit MCS51 MCU with ADC & SPI & USB device & dual UART
footprint LQFP48
pins: 1 P1.6/AIN6/MISO (io), 2 P1.7/AIN7/SCK (io), 3 P5.7/RST (in), 4 P3.0/RXD (io), 5 P4.5/A5 (io), 6 P4.4/LED3/TNOW_/TXD1_/A4 (io), 7 P3.1/TXD (io), 8 P3.2/LED0/INT0 (io), 9 P3.3/LED1/!A15/INT1 (io), 10 P3.4/LEDC/XCS0/T0 (io), 11 P3.5/DA6/T1 (io), 12 P3.6/WR (io), 13 P3.7/RD (io), 14 P4.3/A3 (io), 15 P4.2/PWM3_/CAP3_/A2 (io), 16 P4.6/XI/SCS_ (io), 17 P4.7/XO/SCK_ (io), 18 GND/VSS (power), 19 P4.1/A1 (io), 20 P4.0/LED2/A0/RXD1_ (io), 21 P2.0/A8 (io), 22 P2.1/A9 (io), 23 P2.2/A10 (io), 24 P2.3/A11 (io), 25 P2.4/A12 (io), 26 P2.5/TNOW/A13/T2EX_/CAP2_ (io), 27 P2.6/RXD1/A14 (io), 28 P2.7/TXD1/DA7/A15 (io), 29 P5.5/!A15/XA (io), 30 P5.4/ALE/XB (io), 31 P5.1/DP (io), 32 P5.0/DM (io), 33 P0.7/AD7/UDCD (io), 34 P0.6/AD6/URI (io), 35 P0.5/AD5/UDSR (io), 36 P0.4/AD4/UCTS (io), 37 P0.3/AD3/TXD_ (io), 38 P0.2/AD2/RXD_ (io), 39 P0.1/AD1/URTS (io), 40 P0.0/AD0/UDTR (io), 41 VIN5 (power), 42 VDD33 (power), 43 P1.0/AIN0/T2/CAP1 (io), 44 P1.1/AIN1/T2EX/CAP2 (io), 45 P1.2/AIN2/PWM3/CAP3 (io), 46 P1.3/AIN3 (io), 47 P1.4/AIN4/SCS (io), 48 P1.5/AIN5/MOSI (io)

## CH558T
designator U?
8bit MCS51 MCU with ADC & SPI & USB device & dual UART
footprint SSOP20
footprint DIP20
pins: 1 P1.2/AIN2/PWM3/CAP3 (io), 2 P1.4/AIN4/SCS (io), 3 P1.5/AIN5/MOSI (io), 4 P1.6/AIN6/MISO (io), 5 P1.7/AIN7/SCK (io), 6 P5.7/RST (in), 7 P3.2/LED0/INT0 (io), 8 P3.4/LEDC/T0 (io), 9 P4.6/XI/SCS_ (io), 10 P4.7/XO/SCK_ (io), 11 P2.5/TNOW/T2EX_/CAP2_ (io), 12 P2.6/RXD1 (io), 13 P2.7/TXD1 (io), 14 P5.1/DP (io), 15 P5.0/DM (io), 16 P0.3/TXD_ (io), 17 P0.2/RXD_ (io), 18 GND/VSS (power), 19 VIN5 (power), 20 VDD33 (power)

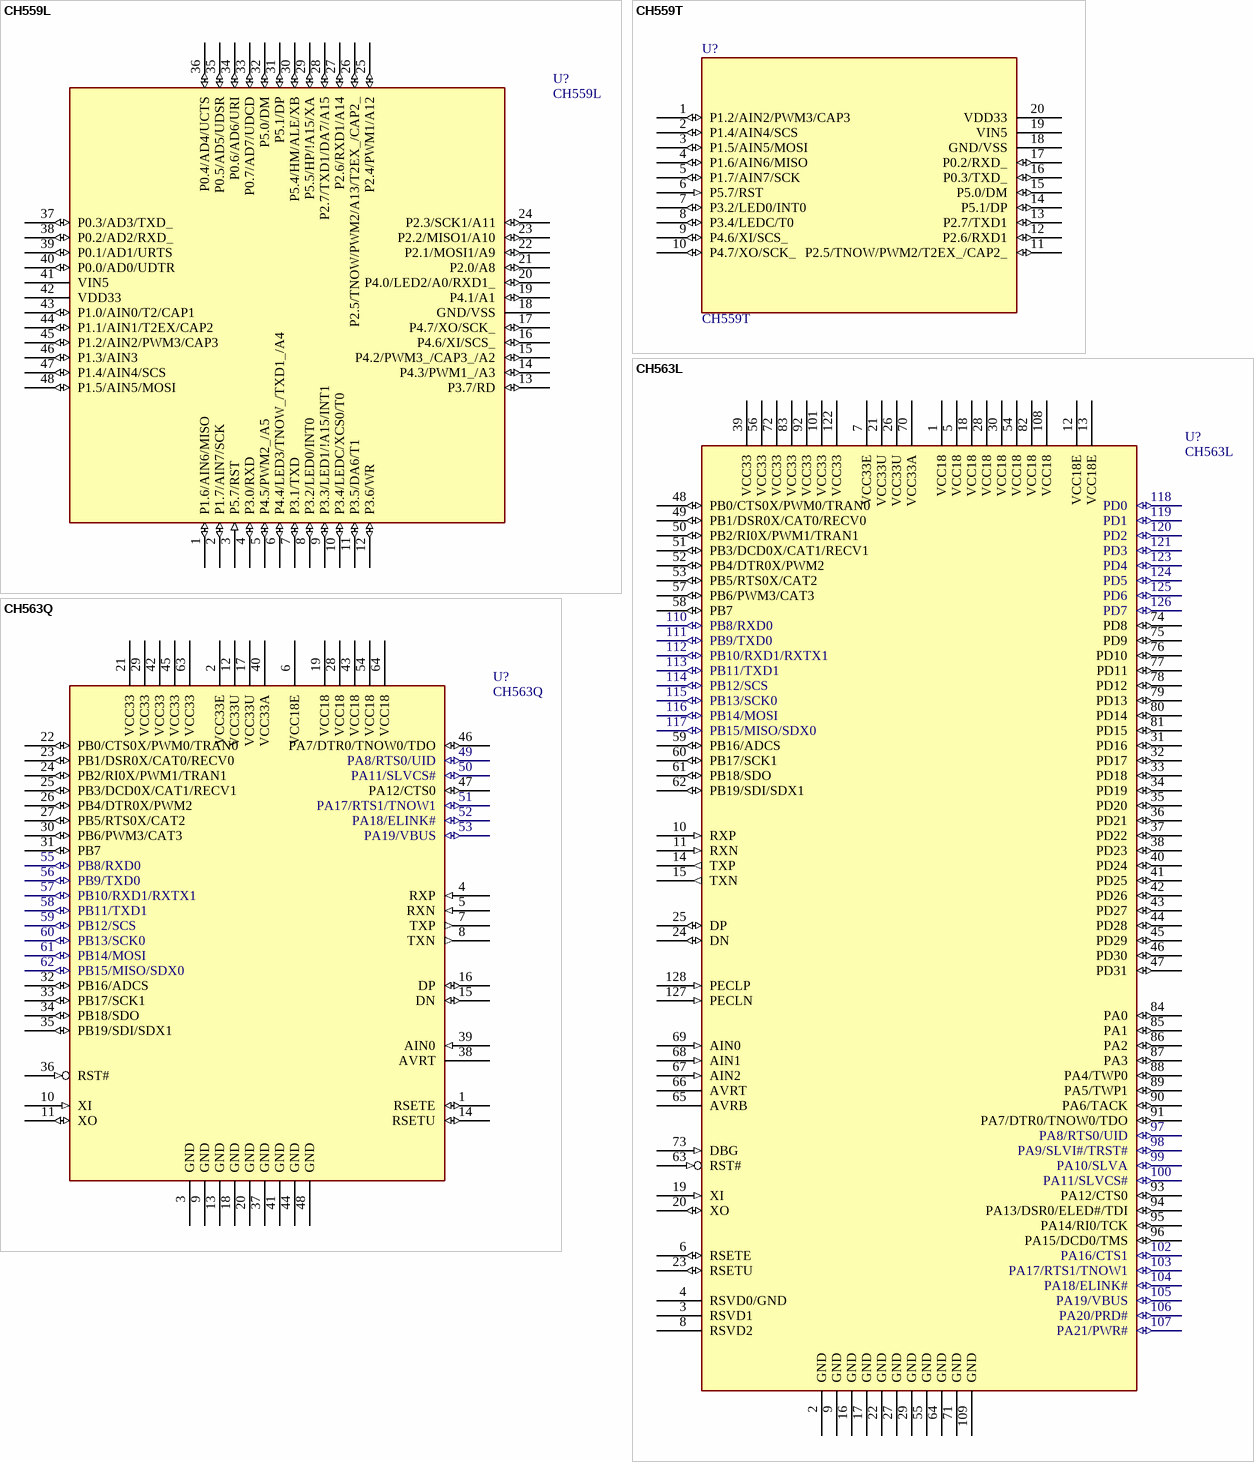
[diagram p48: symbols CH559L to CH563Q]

## CH559L
designator U?
8bit MCS51 MCU with ADC & SPI & 2 * USB host & device & dual UART
footprint LQFP48
pins: 1 P1.6/AIN6/MISO (io), 2 P1.7/AIN7/SCK (io), 3 P5.7/RST (in), 4 P3.0/RXD (io), 5 P4.5/PWM2_/A5 (io), 6 P4.4/LED3/TNOW_/TXD1_/A4 (io), 7 P3.1/TXD (io), 8 P3.2/LED0/INT0 (io), 9 P3.3/LED1/!A15/INT1 (io), 10 P3.4/LEDC/XCS0/T0 (io), 11 P3.5/DA6/T1 (io), 12 P3.6/WR (io), 13 P3.7/RD (io), 14 P4.3/PWM1_/A3 (io), 15 P4.2/PWM3_/CAP3_/A2 (io), 16 P4.6/XI/SCS_ (io), 17 P4.7/XO/SCK_ (io), 18 GND/VSS (power), 19 P4.1/A1 (io), 20 P4.0/LED2/A0/RXD1_ (io), 21 P2.0/A8 (io), 22 P2.1/MOSI1/A9 (io), 23 P2.2/MISO1/A10 (io), 24 P2.3/SCK1/A11 (io), 25 P2.4/PWM1/A12 (io), 26 P2.5/TNOW/PWM2/A13/T2EX_/CAP2_ (io), 27 P2.6/RXD1/A14 (io), 28 P2.7/TXD1/DA7/A15 (io), 29 P5.5/HP/!A15/XA (io), 30 P5.4/HM/ALE/XB (io), 31 P5.1/DP (io), 32 P5.0/DM (io), 33 P0.7/AD7/UDCD (io), 34 P0.6/AD6/URI (io), 35 P0.5/AD5/UDSR (io), 36 P0.4/AD4/UCTS (io), 37 P0.3/AD3/TXD_ (io), 38 P0.2/AD2/RXD_ (io), 39 P0.1/AD1/URTS (io), 40 P0.0/AD0/UDTR (io), 41 VIN5 (power), 42 VDD33 (power), 43 P1.0/AIN0/T2/CAP1 (io), 44 P1.1/AIN1/T2EX/CAP2 (io), 45 P1.2/AIN2/PWM3/CAP3 (io), 46 P1.3/AIN3 (io), 47 P1.4/AIN4/SCS (io), 48 P1.5/AIN5/MOSI (io)

## CH559T
designator U?
8bit MCS51 MCU with ADC & SPI & USB host & device & dual UART
footprint SSOP20
footprint DIP20
pins: 1 P1.2/AIN2/PWM3/CAP3 (io), 2 P1.4/AIN4/SCS (io), 3 P1.5/AIN5/MOSI (io), 4 P1.6/AIN6/MISO (io), 5 P1.7/AIN7/SCK (io), 6 P5.7/RST (in), 7 P3.2/LED0/INT0 (io), 8 P3.4/LEDC/T0 (io), 9 P4.6/XI/SCS_ (io), 10 P4.7/XO/SCK_ (io), 11 P2.5/TNOW/PWM2/T2EX_/CAP2_ (io), 12 P2.6/RXD1 (io), 13 P2.7/TXD1 (io), 14 P5.1/DP (io), 15 P5.0/DM (io), 16 P0.3/TXD_ (io), 17 P0.2/RXD_ (io), 18 GND/VSS (power), 19 VIN5 (power), 20 VDD33 (power)

## CH563L
designator U?
32bit MCU with USB OTG 2.0 & 100Mbps Ethernet
footprint LQFP128
pins: 1 VCC18 (power), 2 GND (power), 3 RSVD1, 4 RSVD0/GND (power), 5 VCC18 (power), 6 RSETE (io), 7 VCC33E (power), 8 RSVD2, 9 GND (power), 10 RXP (in), 11 RXN (in), 12 VCC18E (power), 13 VCC18E (power), 14 TXP (out), 15 TXN (out), 16 GND (power), 17 GND (power), 18 VCC18 (power), 19 XI (in), 20 XO (io), 21 VCC33U (power), 22 GND (power), 23 RSETU (io), 24 DN (io), 25 DP (io), 26 VCC33U (power), 27 GND (power), 28 VCC18 (power), 29 GND (power), 30 VCC18 (power), 31 PD16 (io), 32 PD17 (io), 33 PD18 (io), 34 PD19 (io), 35 PD20 (io), 36 PD21 (io), 37 PD22 (io), 38 PD23 (io), 39 VCC33 (power), 40 PD24 (io), 41 PD25 (io), 42 PD26 (io), 43 PD27 (io), 44 PD28 (io), 45 PD29 (io), 46 PD30 (io), 47 PD31 (io), 48 PB0/CTS0X/PWM0/TRAN0 (io), 49 PB1/DSR0X/CAT0/RECV0 (io), 50 PB2/RI0X/PWM1/TRAN1 (io), 51 PB3/DCD0X/CAT1/RECV1 (io), 52 PB4/DTR0X/PWM2 (io), 53 PB5/RTS0X/CAT2 (io), 54 VCC18 (power), 55 GND (power), 56 VCC33 (power), 57 PB6/PWM3/CAT3 (io), 58 PB7 (io), 59 PB16/ADCS (io), 60 PB17/SCK1 (io), 61 PB18/SDO (io), 62 PB19/SDI/SDX1 (io), 63 RST# (in), 64 GND (power), 65 AVRB (power), 66 AVRT (power), 67 AIN2 (in), 68 AIN1 (in), 69 AIN0 (in), 70 VCC33A (power), 71 GND (power), 72 VCC33 (power), 73 DBG (in), 74 PD8 (io), 75 PD9 (io), 76 PD10 (io), 77 PD11 (io), 78 PD12 (io), 79 PD13 (io), 80 PD14 (io), 81 PD15 (io), 82 VCC18 (power), 83 VCC33 (power), 84 PA0 (io), 85 PA1 (io), 86 PA2 (io), 87 PA3 (io), 88 PA4/TWP0 (io), 89 PA5/TWP1 (io), 90 PA6/TACK (io), 91 PA7/DTR0/TNOW0/TDO (io), 92 VCC33 (power), 93 PA12/CTS0 (io), 94 PA13/DSR0/ELED#/TDI (io), 95 PA14/RI0/TCK (io), 96 PA15/DCD0/TMS (io), 97 PA8/RTS0/UID (io), 98 PA9/SLVI#/TRST# (io), 99 PA10/SLVA (io), 100 PA11/SLVCS# (io), 101 VCC33 (power), 102 PA16/CTS1 (io), 103 PA17/RTS1/TNOW1 (io), 104 PA18/ELINK# (io), 105 PA19/VBUS (io), 106 PA20/PRD# (io), 107 PA21/PWR# (io), 108 VCC18 (power), 109 GND (power), 110 PB8/RXD0 (io), 111 PB9/TXD0 (io), 112 PB10/RXD1/RXTX1 (io), 113 PB11/TXD1 (io), 114 PB12/SCS (io), 115 PB13/SCK0 (io), 116 PB14/MOSI (io), 117 PB15/MISO/SDX0 (io), 118 PD0 (io), 119 PD1 (io), 120 PD2 (io), 121 PD3 (io), 122 VCC33 (power), 123 PD4 (io), 124 PD5 (io), 125 PD6 (io), 126 PD7 (io), 127 PECLN (in), 128 PECLP (in)

## CH563Q
designator U?
32bit MCU with USB OTG 2.0 & 100Mbps Ethernet
footprint LQFP64M_10X10
pins: 1 RSETE (io), 2 VCC33E (power), 3 GND (power), 4 RXP (in), 5 RXN (in), 6 VCC18E (power), 7 TXP (out), 8 TXN (out), 9 GND (power), 10 XI (in), 11 XO (io), 12 VCC33U (power), 13 GND (power), 14 RSETU (io), 15 DN (io), 16 DP (io), 17 VCC33U (power), 18 GND (power), 19 VCC18 (power), 20 GND (power), 21 VCC33 (power), 22 PB0/CTS0X/PWM0/TRAN0 (io), 23 PB1/DSR0X/CAT0/RECV0 (io), 24 PB2/RI0X/PWM1/TRAN1 (io), 25 PB3/DCD0X/CAT1/RECV1 (io), 26 PB4/DTR0X/PWM2 (io), 27 PB5/RTS0X/CAT2 (io), 28 VCC18 (power), 29 VCC33 (power), 30 PB6/PWM3/CAT3 (io), 31 PB7 (io), 32 PB16/ADCS (io), 33 PB17/SCK1 (io), 34 PB18/SDO (io), 35 PB19/SDI/SDX1 (io), 36 RST# (in), 37 GND (power), 38 AVRT (power), 39 AIN0 (in), 40 VCC33A (power), 41 GND (power), 42 VCC33 (power), 43 VCC18 (power), 44 GND (power), 45 VCC33 (power), 46 PA7/DTR0/TNOW0/TDO (io), 47 PA12/CTS0 (io), 48 GND (power), 49 PA8/RTS0/UID (io), 50 PA11/SLVCS# (io), 51 PA17/RTS1/TNOW1 (io), 52 PA18/ELINK# (io), 53 PA19/VBUS (io), 54 VCC18 (power), 55 PB8/RXD0 (io), 56 PB9/TXD0 (io), 57 PB10/RXD1/RXTX1 (io), 58 PB11/TXD1 (io), 59 PB12/SCS (io), 60 PB13/SCK0 (io), 61 PB14/MOSI (io), 62 PB15/MISO/SDX0 (io), 63 VCC33 (power), 64 VCC18 (power)

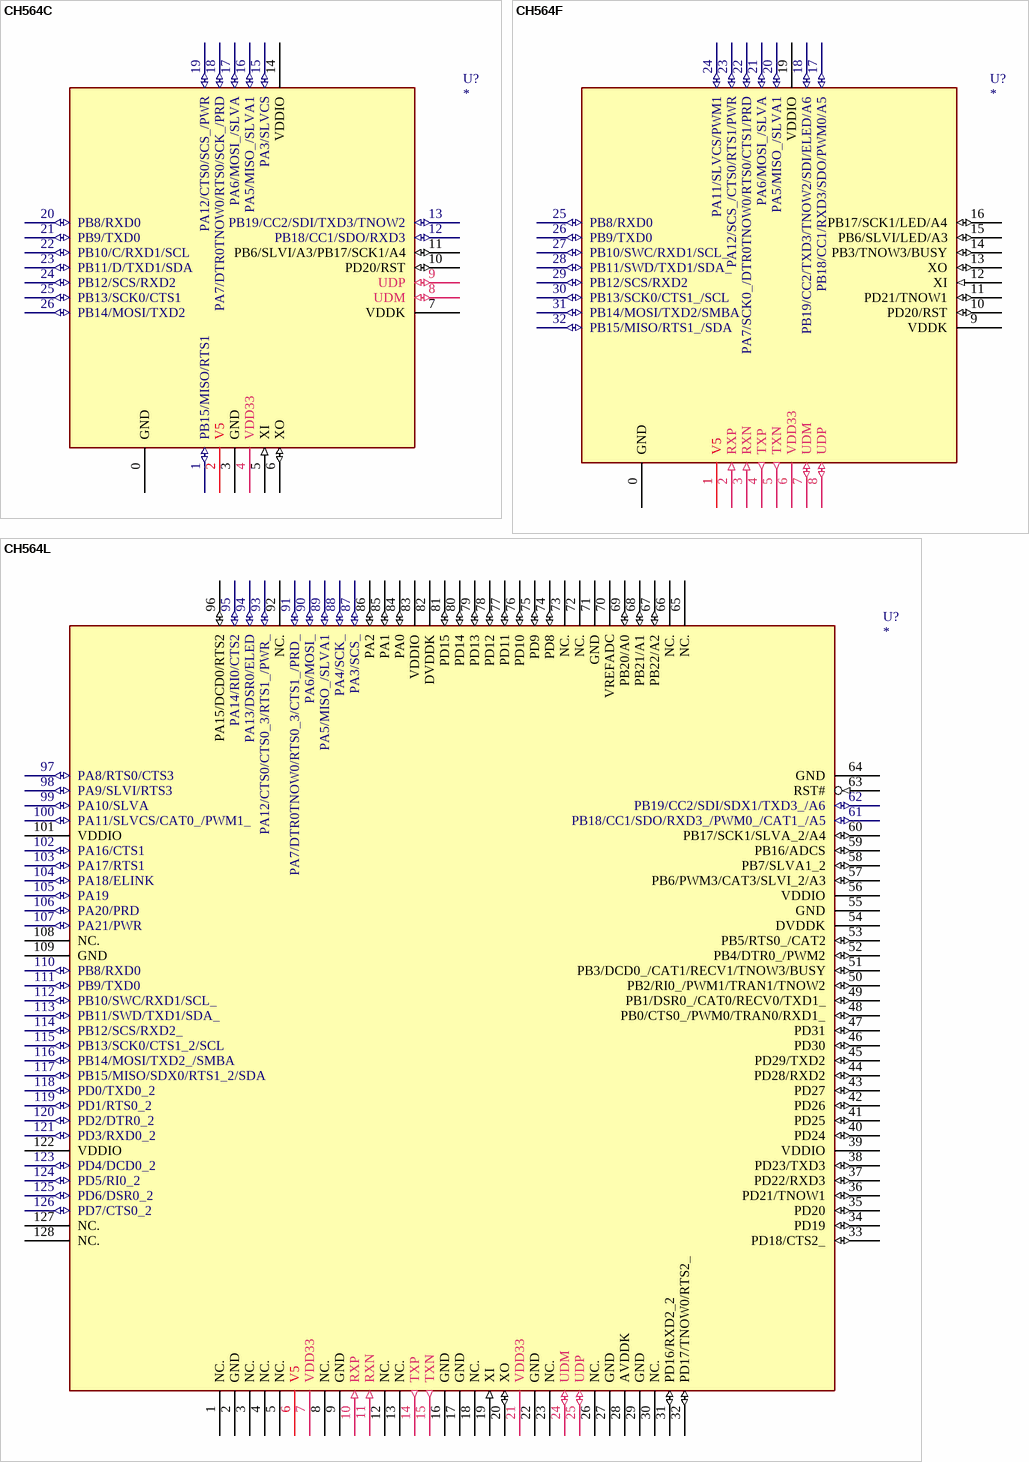
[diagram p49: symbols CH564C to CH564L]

## CH564C
designator U?
RISC-V MCU for high-speed USB to UART & SPI & Parallel
footprint QFN26C_3X3
pins: 0 GND (power), 1 PB15/MISO/RTS1 (io), 2 V5 (power), 3 GND (power), 4 VDD33 (power), 5 XI (in), 6 XO (io), 7 VDDK (power), 8 UDM (io), 9 UDP (io), 10 PD20/RST (io), 11 PB6/SLVI/A3/PB17/SCK1/A4 (io), 12 PB18/CC1/SDO/RXD3 (io), 13 PB19/CC2/SDI/TXD3/TNOW2 (io), 14 VDDIO (power), 15 PA3/SLVCS (io), 16 PA5/MISO_/SLVA1 (io), 17 PA6/MOSI_/SLVA (io), 18 PA7/DTR0TNOW0/RTS0/SCK_/PRD (io), 19 PA12/CTS0/SCS_/PWR (io), 20 PB8/RXD0 (io), 21 PB9/TXD0 (io), 22 PB10/C/RXD1/SCL (io), 23 PB11/D/TXD1/SDA (io), 24 PB12/SCS/RXD2 (io), 25 PB13/SCK0/CTS1 (io), 26 PB14/MOSI/TXD2 (io)

## CH564F
designator U?
RISC-V MCU with USB OTG 2.0 & 100Mbps Ethernet
footprint QFN32_4X4 (Footprint not found)
pins: 0 GND (power), 1 V5 (power), 2 RXP (in), 3 RXN (in), 4 TXP (out), 5 TXN (out), 6 VDD33 (power), 7 UDM (io), 8 UDP (io), 9 VDDK (power), 10 PD20/RST (io), 11 PD21/TNOW1 (io), 12 XI (in), 13 XO (io), 14 PB3/TNOW3/BUSY (io), 15 PB6/SLVI/LED/A3 (io), 16 PB17/SCK1/LED/A4 (io), 17 PB18/CC1/RXD3/SDO/PWM0/A5 (io), 18 PB19/CC2/TXD3/TNOW2/SDI/ELED/A6 (io), 19 VDDIO (power), 20 PA5/MISO_/SLVA1 (io), 21 PA6/MOSI_/SLVA (io), 22 PA7/SCK0_/DTR0TNOW0/RTS0/CTS1/PRD (io), 23 PA12/SCS_/CTS0/RTS1/PWR (io), 24 PA11/SLVCS/PWM1 (io), 25 PB8/RXD0 (io), 26 PB9/TXD0 (io), 27 PB10/SWC/RXD1/SCL_ (io), 28 PB11/SWD/TXD1/SDA_ (io), 29 PB12/SCS/RXD2 (io), 30 PB13/SCK0/CTS1_/SCL (io), 31 PB14/MOSI/TXD2/SMBA (io), 32 PB15/MISO/RTS1_/SDA (io)

## CH564L
designator U?
RISC-V MCU with USB OTG 2.0 & 100Mbps Ethernet
footprint LQFP128
pins: 1 NC., 2 GND (power), 3 NC., 4 NC., 5 NC., 6 V5 (power), 7 VDD33 (power), 8 NC., 9 GND (power), 10 RXP (in), 11 RXN (in), 12 NC., 13 NC., 14 TXP (out), 15 TXN (out), 16 GND (power), 17 GND (power), 18 NC., 19 XI (in), 20 XO (io), 21 VDD33 (power), 22 GND (power), 23 NC., 24 UDM (io), 25 UDP (io), 26 NC., 27 GND (power), 28 AVDDK (power), 29 GND (power), 30 NC., 31 PD16/RXD2_2 (io), 32 PD17/TNOW0/RTS2_ (io), 33 PD18/CTS2_ (io), 34 PD19 (io), 35 PD20 (io), 36 PD21/TNOW1 (io), 37 PD22/RXD3 (io), 38 PD23/TXD3 (io), 39 VDDIO (power), 40 PD24 (io), 41 PD25 (io), 42 PD26 (io), 43 PD27 (io), 44 PD28/RXD2 (io), 45 PD29/TXD2 (io), 46 PD30 (io), 47 PD31 (io), 48 PB0/CTS0_/PWM0/TRAN0/RXD1_ (io), 49 PB1/DSR0_/CAT0/RECV0/TXD1_ (io), 50 PB2/RI0_/PWM1/TRAN1/TNOW2 (io), 51 PB3/DCD0_/CAT1/RECV1/TNOW3/BUSY (io), 52 PB4/DTR0_/PWM2 (io), 53 PB5/RTS0_/CAT2 (io), 54 DVDDK (power), 55 GND (power), 56 VDDIO (power), 57 PB6/PWM3/CAT3/SLVI_2/A3 (io), 58 PB7/SLVA1_2 (io), 59 PB16/ADCS (io), 60 PB17/SCK1/SLVA_2/A4 (io), 61 PB18/CC1/SDO/RXD3_/PWM0_/CAT1_/A5 (io), 62 PB19/CC2/SDI/SDX1/TXD3_/A6 (io), 63 RST# (in), 64 GND (power), 65 NC., 66 NC., 67 PB22/A2 (io), 68 PB21/A1 (io), 69 PB20/A0 (io), 70 VREFADC (power), 71 GND (power), 72 NC., 73 NC., 74 PD8 (io), 75 PD9 (io), 76 PD10 (io), 77 PD11 (io), 78 PD12 (io), 79 PD13 (io), 80 PD14 (io), 81 PD15 (io), 82 DVDDK (power), 83 VDDIO (power), 84 PA0 (io), 85 PA1 (io), 86 PA2 (io), 87 PA3/SCS_ (io), 88 PA4/SCK_ (io), 89 PA5/MISO_/SLVA1 (io), 90 PA6/MOSI_ (io), 91 PA7/DTR0TNOW0/RTS0_3/CTS1_/PRD_ (io), 92 NC., 93 PA12/CTS0/CTS0_3/RTS1_/PWR_ (io), 94 PA13/DSR0/ELED (io), 95 PA14/RI0/CTS2 (io), 96 PA15/DCD0/RTS2 (io), 97 PA8/RTS0/CTS3 (io), 98 PA9/SLVI/RTS3 (io), 99 PA10/SLVA (io), 100 PA11/SLVCS/CAT0_/PWM1_ (io), 101 VDDIO (power), 102 PA16/CTS1 (io), 103 PA17/RTS1 (io), 104 PA18/ELINK (io), 105 PA19 (io), 106 PA20/PRD (io), 107 PA21/PWR (io), 108 NC., 109 GND (power), 110 PB8/RXD0 (io), 111 PB9/TXD0 (io), 112 PB10/SWC/RXD1/SCL_ (io), 113 PB11/SWD/TXD1/SDA_ (io), 114 PB12/SCS/RXD2_ (io), 115 PB13/SCK0/CTS1_2/SCL (io), 116 PB14/MOSI/TXD2_/SMBA (io), 117 PB15/MISO/SDX0/RTS1_2/SDA (io), 118 PD0/TXD0_2 (io), 119 PD1/RTS0_2 (io), 120 PD2/DTR0_2 (io), 121 PD3/RXD0_2 (io), 122 VDDIO (power), 123 PD4/DCD0_2 (io), 124 PD5/RI0_2 (io), 125 PD6/DSR0_2 (io), 126 PD7/CTS0_2 (io), 127 NC., 128 NC.

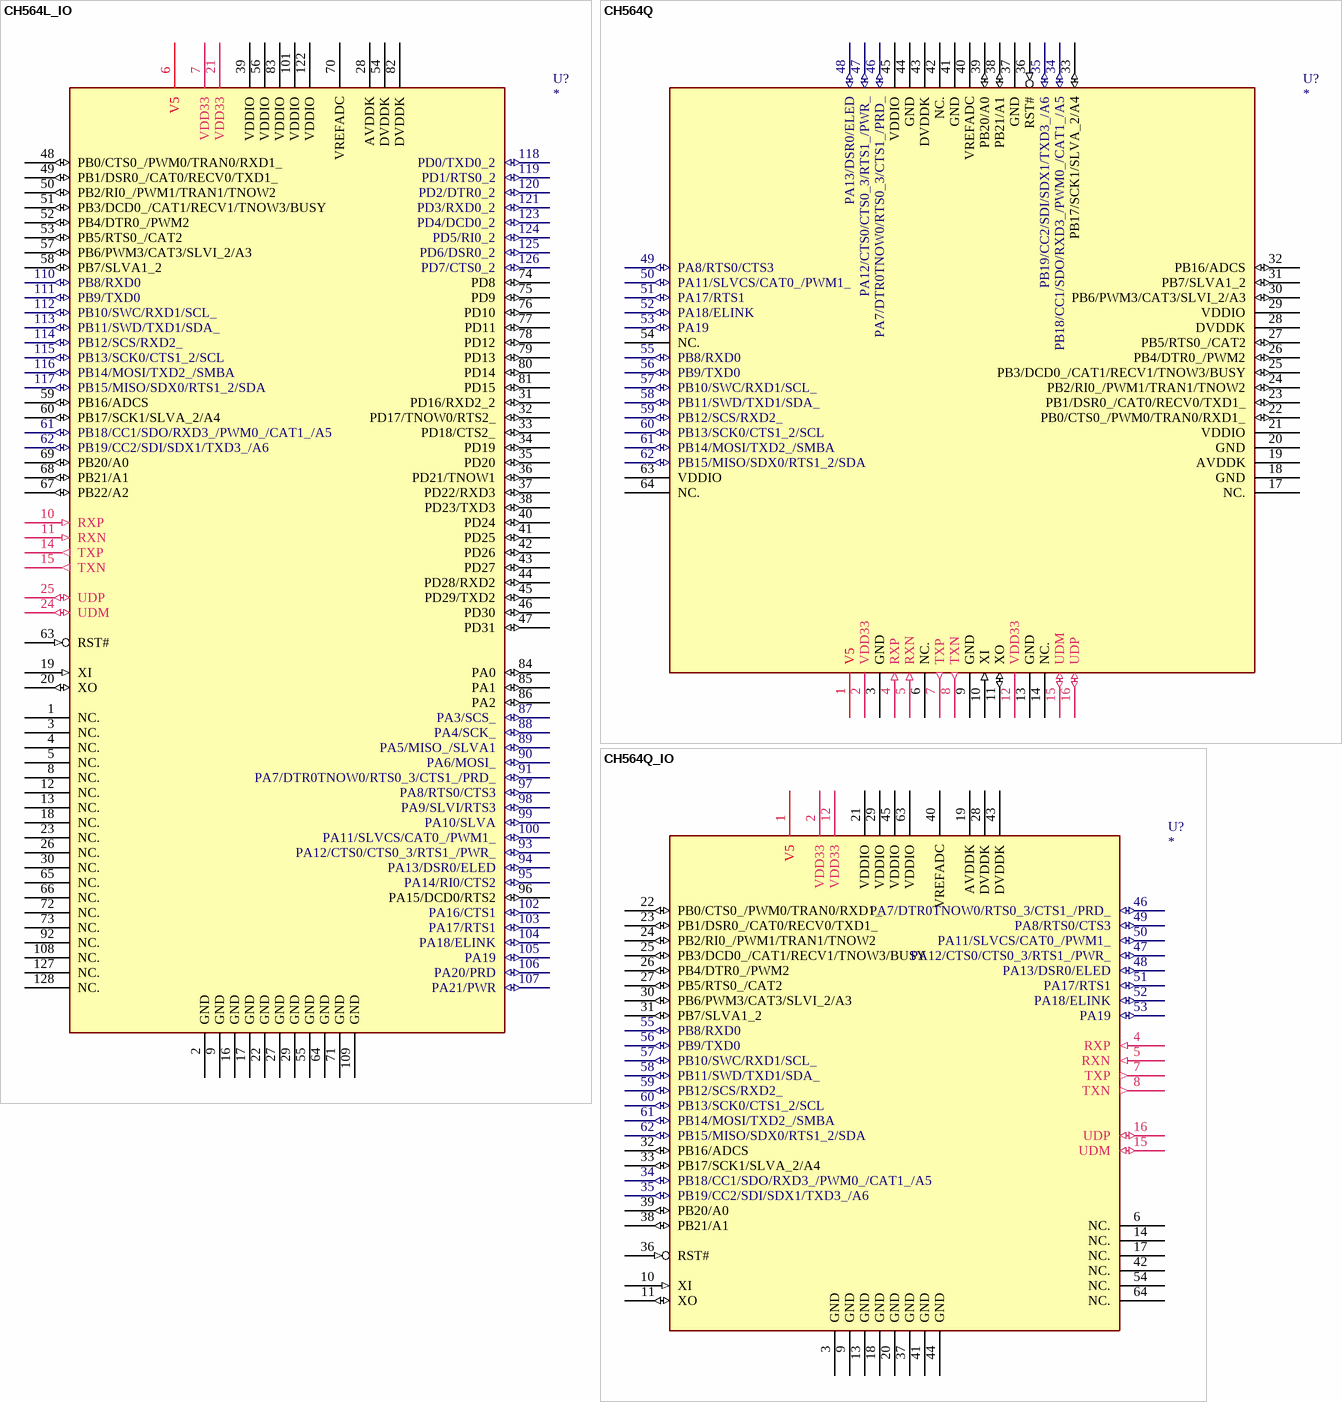
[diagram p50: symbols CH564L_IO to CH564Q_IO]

## CH564L_IO
designator U?
RISC-V MCU with USB OTG 2.0 & 100Mbps Ethernet
footprint LQFP128
pins: 1 NC., 2 GND (power), 3 NC., 4 NC., 5 NC., 6 V5 (power), 7 VDD33 (power), 8 NC., 9 GND (power), 10 RXP (in), 11 RXN (in), 12 NC., 13 NC., 14 TXP (out), 15 TXN (out), 16 GND (power), 17 GND (power), 18 NC., 19 XI (in), 20 XO (io), 21 VDD33 (power), 22 GND (power), 23 NC., 24 UDM (io), 25 UDP (io), 26 NC., 27 GND (power), 28 AVDDK (power), 29 GND (power), 30 NC., 31 PD16/RXD2_2 (io), 32 PD17/TNOW0/RTS2_ (io), 33 PD18/CTS2_ (io), 34 PD19 (io), 35 PD20 (io), 36 PD21/TNOW1 (io), 37 PD22/RXD3 (io), 38 PD23/TXD3 (io), 39 VDDIO (power), 40 PD24 (io), 41 PD25 (io), 42 PD26 (io), 43 PD27 (io), 44 PD28/RXD2 (io), 45 PD29/TXD2 (io), 46 PD30 (io), 47 PD31 (io), 48 PB0/CTS0_/PWM0/TRAN0/RXD1_ (io), 49 PB1/DSR0_/CAT0/RECV0/TXD1_ (io), 50 PB2/RI0_/PWM1/TRAN1/TNOW2 (io), 51 PB3/DCD0_/CAT1/RECV1/TNOW3/BUSY (io), 52 PB4/DTR0_/PWM2 (io), 53 PB5/RTS0_/CAT2 (io), 54 DVDDK (power), 55 GND (power), 56 VDDIO (power), 57 PB6/PWM3/CAT3/SLVI_2/A3 (io), 58 PB7/SLVA1_2 (io), 59 PB16/ADCS (io), 60 PB17/SCK1/SLVA_2/A4 (io), 61 PB18/CC1/SDO/RXD3_/PWM0_/CAT1_/A5 (io), 62 PB19/CC2/SDI/SDX1/TXD3_/A6 (io), 63 RST# (in), 64 GND (power), 65 NC., 66 NC., 67 PB22/A2 (io), 68 PB21/A1 (io), 69 PB20/A0 (io), 70 VREFADC (power), 71 GND (power), 72 NC., 73 NC., 74 PD8 (io), 75 PD9 (io), 76 PD10 (io), 77 PD11 (io), 78 PD12 (io), 79 PD13 (io), 80 PD14 (io), 81 PD15 (io), 82 DVDDK (power), 83 VDDIO (power), 84 PA0 (io), 85 PA1 (io), 86 PA2 (io), 87 PA3/SCS_ (io), 88 PA4/SCK_ (io), 89 PA5/MISO_/SLVA1 (io), 90 PA6/MOSI_ (io), 91 PA7/DTR0TNOW0/RTS0_3/CTS1_/PRD_ (io), 92 NC., 93 PA12/CTS0/CTS0_3/RTS1_/PWR_ (io), 94 PA13/DSR0/ELED (io), 95 PA14/RI0/CTS2 (io), 96 PA15/DCD0/RTS2 (io), 97 PA8/RTS0/CTS3 (io), 98 PA9/SLVI/RTS3 (io), 99 PA10/SLVA (io), 100 PA11/SLVCS/CAT0_/PWM1_ (io), 101 VDDIO (power), 102 PA16/CTS1 (io), 103 PA17/RTS1 (io), 104 PA18/ELINK (io), 105 PA19 (io), 106 PA20/PRD (io), 107 PA21/PWR (io), 108 NC., 109 GND (power), 110 PB8/RXD0 (io), 111 PB9/TXD0 (io), 112 PB10/SWC/RXD1/SCL_ (io), 113 PB11/SWD/TXD1/SDA_ (io), 114 PB12/SCS/RXD2_ (io), 115 PB13/SCK0/CTS1_2/SCL (io), 116 PB14/MOSI/TXD2_/SMBA (io), 117 PB15/MISO/SDX0/RTS1_2/SDA (io), 118 PD0/TXD0_2 (io), 119 PD1/RTS0_2 (io), 120 PD2/DTR0_2 (io), 121 PD3/RXD0_2 (io), 122 VDDIO (power), 123 PD4/DCD0_2 (io), 124 PD5/RI0_2 (io), 125 PD6/DSR0_2 (io), 126 PD7/CTS0_2 (io), 127 NC., 128 NC.

## CH564Q
designator U?
RISC-V MCU with USB OTG 2.0 & 100Mbps Ethernet
footprint LQFP64M_10X10
pins: 1 V5 (power), 2 VDD33 (power), 3 GND (power), 4 RXP (in), 5 RXN (in), 6 NC., 7 TXP (out), 8 TXN (out), 9 GND (power), 10 XI (in), 11 XO (io), 12 VDD33 (power), 13 GND (power), 14 NC., 15 UDM (io), 16 UDP (io), 17 NC., 18 GND (power), 19 AVDDK (power), 20 GND (power), 21 VDDIO (power), 22 PB0/CTS0_/PWM0/TRAN0/RXD1_ (io), 23 PB1/DSR0_/CAT0/RECV0/TXD1_ (io), 24 PB2/RI0_/PWM1/TRAN1/TNOW2 (io), 25 PB3/DCD0_/CAT1/RECV1/TNOW3/BUSY (io), 26 PB4/DTR0_/PWM2 (io), 27 PB5/RTS0_/CAT2 (io), 28 DVDDK (power), 29 VDDIO (power), 30 PB6/PWM3/CAT3/SLVI_2/A3 (io), 31 PB7/SLVA1_2 (io), 32 PB16/ADCS (io), 33 PB17/SCK1/SLVA_2/A4 (io), 34 PB18/CC1/SDO/RXD3_/PWM0_/CAT1_/A5 (io), 35 PB19/CC2/SDI/SDX1/TXD3_/A6 (io), 36 RST# (in), 37 GND (power), 38 PB21/A1 (io), 39 PB20/A0 (io), 40 VREFADC (power), 41 GND (power), 42 NC., 43 DVDDK (power), 44 GND (power), 45 VDDIO (power), 46 PA7/DTR0TNOW0/RTS0_3/CTS1_/PRD_ (io), 47 PA12/CTS0/CTS0_3/RTS1_/PWR_ (io), 48 PA13/DSR0/ELED (io), 49 PA8/RTS0/CTS3 (io), 50 PA11/SLVCS/CAT0_/PWM1_ (io), 51 PA17/RTS1 (io), 52 PA18/ELINK (io), 53 PA19 (io), 54 NC., 55 PB8/RXD0 (io), 56 PB9/TXD0 (io), 57 PB10/SWC/RXD1/SCL_ (io), 58 PB11/SWD/TXD1/SDA_ (io), 59 PB12/SCS/RXD2_ (io), 60 PB13/SCK0/CTS1_2/SCL (io), 61 PB14/MOSI/TXD2_/SMBA (io), 62 PB15/MISO/SDX0/RTS1_2/SDA (io), 63 VDDIO (power), 64 NC.

## CH564Q_IO
designator U?
RISC-V MCU with USB OTG 2.0 & 100Mbps Ethernet
footprint LQFP64M_10X10
pins: 1 V5 (power), 2 VDD33 (power), 3 GND (power), 4 RXP (in), 5 RXN (in), 6 NC., 7 TXP (out), 8 TXN (out), 9 GND (power), 10 XI (in), 11 XO (io), 12 VDD33 (power), 13 GND (power), 14 NC., 15 UDM (io), 16 UDP (io), 17 NC., 18 GND (power), 19 AVDDK (power), 20 GND (power), 21 VDDIO (power), 22 PB0/CTS0_/PWM0/TRAN0/RXD1_ (io), 23 PB1/DSR0_/CAT0/RECV0/TXD1_ (io), 24 PB2/RI0_/PWM1/TRAN1/TNOW2 (io), 25 PB3/DCD0_/CAT1/RECV1/TNOW3/BUSY (io), 26 PB4/DTR0_/PWM2 (io), 27 PB5/RTS0_/CAT2 (io), 28 DVDDK (power), 29 VDDIO (power), 30 PB6/PWM3/CAT3/SLVI_2/A3 (io), 31 PB7/SLVA1_2 (io), 32 PB16/ADCS (io), 33 PB17/SCK1/SLVA_2/A4 (io), 34 PB18/CC1/SDO/RXD3_/PWM0_/CAT1_/A5 (io), 35 PB19/CC2/SDI/SDX1/TXD3_/A6 (io), 36 RST# (in), 37 GND (power), 38 PB21/A1 (io), 39 PB20/A0 (io), 40 VREFADC (power), 41 GND (power), 42 NC., 43 DVDDK (power), 44 GND (power), 45 VDDIO (power), 46 PA7/DTR0TNOW0/RTS0_3/CTS1_/PRD_ (io), 47 PA12/CTS0/CTS0_3/RTS1_/PWR_ (io), 48 PA13/DSR0/ELED (io), 49 PA8/RTS0/CTS3 (io), 50 PA11/SLVCS/CAT0_/PWM1_ (io), 51 PA17/RTS1 (io), 52 PA18/ELINK (io), 53 PA19 (io), 54 NC., 55 PB8/RXD0 (io), 56 PB9/TXD0 (io), 57 PB10/SWC/RXD1/SCL_ (io), 58 PB11/SWD/TXD1/SDA_ (io), 59 PB12/SCS/RXD2_ (io), 60 PB13/SCK0/CTS1_2/SCL (io), 61 PB14/MOSI/TXD2_/SMBA (io), 62 PB15/MISO/SDX0/RTS1_2/SDA (io), 63 VDDIO (power), 64 NC.

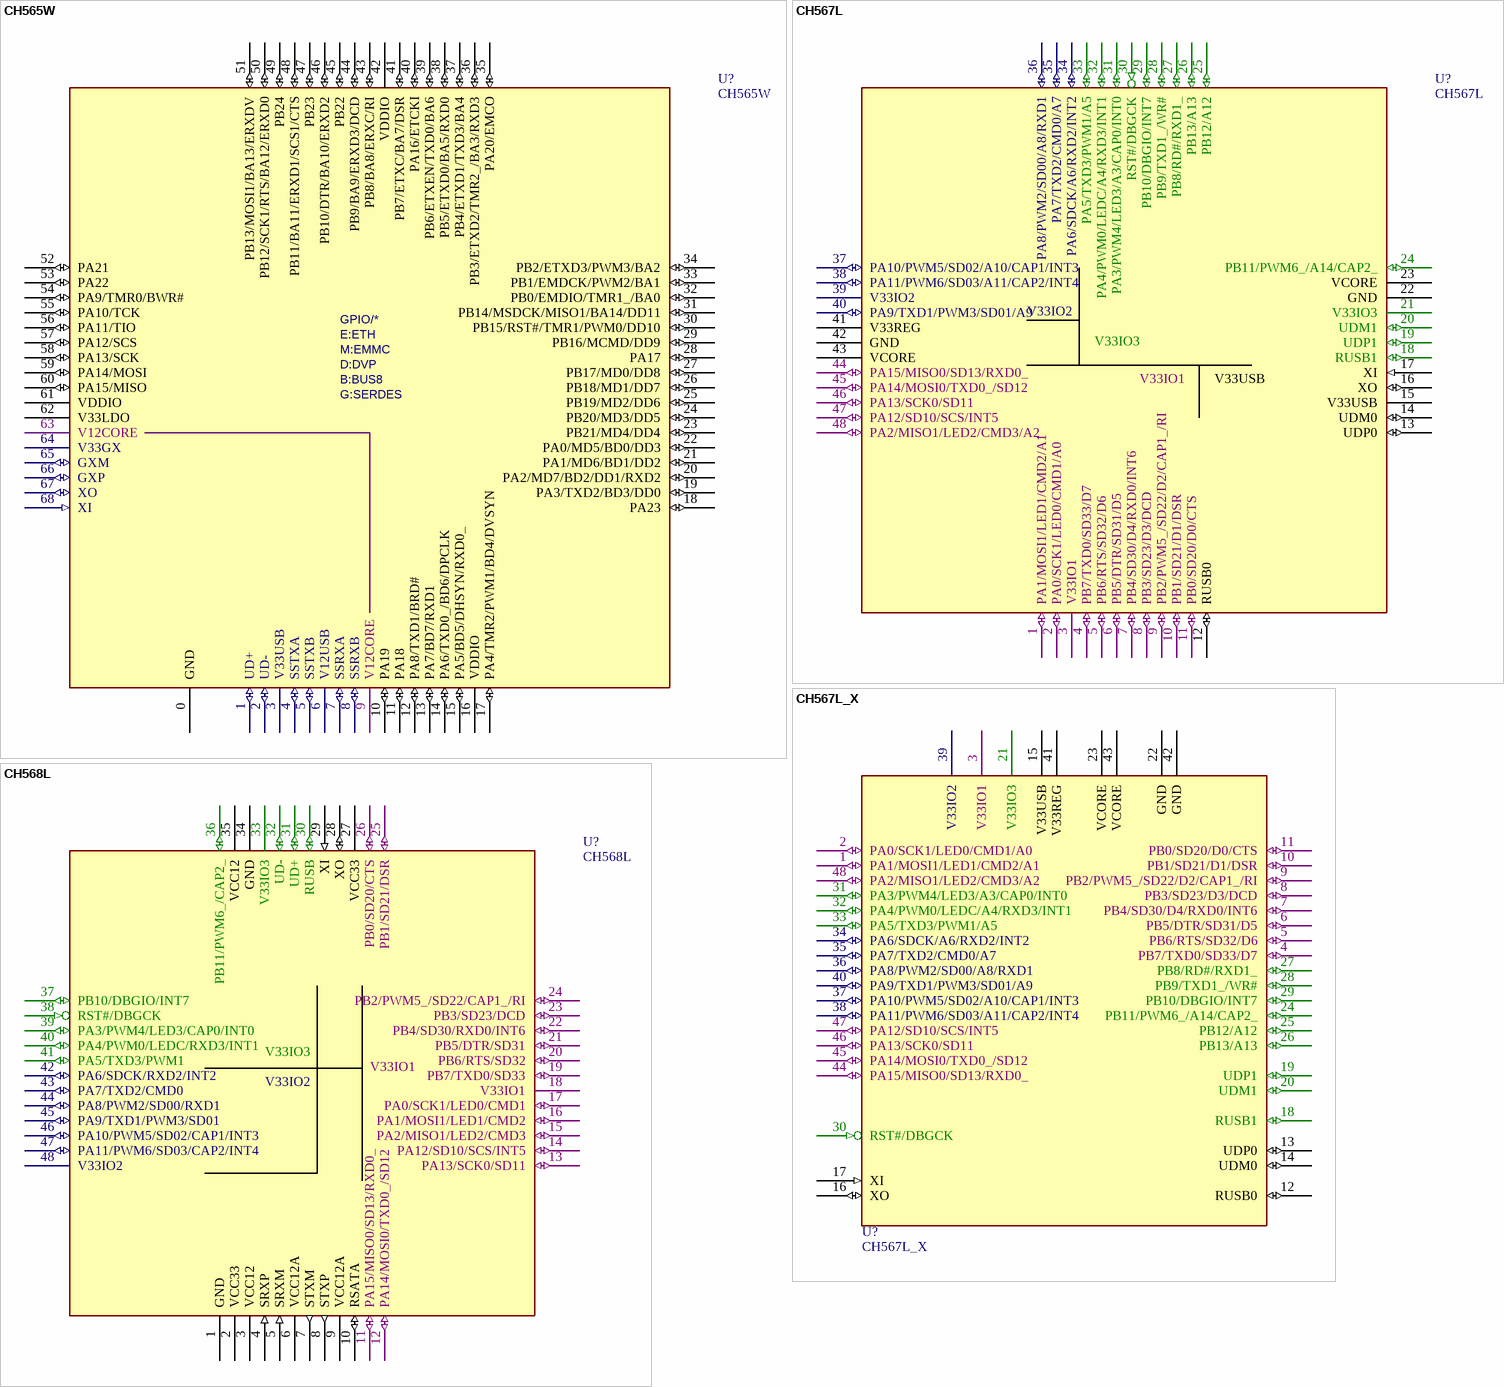
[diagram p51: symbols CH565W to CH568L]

## CH565W
designator U?
32bit RISC-V MCU with USB 3.0 SS/HS & 4*UART & ETH & DVP
footprint QFN68_8X8
pins: 0 GND (power), 1 UD+ (io), 2 UD- (io), 3 V33USB (power), 4 SSTXA (io), 5 SSTXB (io), 6 V12USB (power), 7 SSRXA (io), 8 SSRXB (io), 9 V12CORE (power), 10 PA19 (io), 11 PA18 (io), 12 PA8/TXD1/BRD# (io), 13 PA7/BD7/RXD1 (io), 14 PA6/TXD0_/BD6/DPCLK (io), 15 PA5/BD5/DHSYN/RXD0_ (io), 16 VDDIO (power), 17 PA4/TMR2/PWM1/BD4/DVSYN (io), 18 PA23 (io), 19 PA3/TXD2/BD3/DD0 (io), 20 PA2/MD7/BD2/DD1/RXD2 (io), 21 PA1/MD6/BD1/DD2 (io), 22 PA0/MD5/BD0/DD3 (io), 23 PB21/MD4/DD4 (io), 24 PB20/MD3/DD5 (io), 25 PB19/MD2/DD6 (io), 26 PB18/MD1/DD7 (io), 27 PB17/MD0/DD8 (io), 28 PA17 (io), 29 PB16/MCMD/DD9 (io), 30 PB15/RST#/TMR1/PWM0/DD10 (io), 31 PB14/MSDCK/MISO1/BA14/DD11 (io), 32 PB0/EMDIO/TMR1_/BA0 (io), 33 PB1/EMDCK/PWM2/BA1 (io), 34 PB2/ETXD3/PWM3/BA2 (io), 35 PA20/EMCO (io), 36 PB3/ETXD2/TMR2_/BA3/RXD3 (io), 37 PB4/ETXD1/TXD3/BA4 (io), 38 PB5/ETXD0/BA5/RXD0 (io), 39 PB6/ETXEN/TXD0/BA6 (io), 40 PA16/ETCKI (io), 41 PB7/ETXC/BA7/DSR (io), 42 VDDIO (power), 43 PB8/BA8/ERXC/RI (io), 44 PB9/BA9/ERXD3/DCD (io), 45 PB22 (io), 46 PB10/DTR/BA10/ERXD2 (io), 47 PB23 (io), 48 PB11/BA11/ERXD1/SCS1/CTS (io), 49 PB24 (io), 50 PB12/SCK1/RTS/BA12/ERXD0 (io), 51 PB13/MOSI1/BA13/ERXDV (io), 52 PA21 (io), 53 PA22 (io), 54 PA9/TMR0/BWR# (io), 55 PA10/TCK (io), 56 PA11/TIO (io), 57 PA12/SCS (io), 58 PA13/SCK (io), 59 PA14/MOSI (io), 60 PA15/MISO (io), 61 VDDIO (power), 62 V33LDO (power), 63 V12CORE (power), 64 V33GX (power), 65 GXM (io), 66 GXP (io), 67 XO (io), 68 XI (in)

## CH567L
designator U?
32bit MCU with dual USB OTG 2.0 & quad SDIO & quad UART & AES
footprint LQFP48
pins: 1 PA1/MOSI1/LED1/CMD2/A1 (io), 2 PA0/SCK1/LED0/CMD1/A0 (io), 3 V33IO1 (power), 4 PB7/TXD0/SD33/D7 (io), 5 PB6/RTS/SD32/D6 (io), 6 PB5/DTR/SD31/D5 (io), 7 PB4/SD30/D4/RXD0/INT6 (io), 8 PB3/SD23/D3/DCD (io), 9 PB2/PWM5_/SD22/D2/CAP1_/RI (io), 10 PB1/SD21/D1/DSR (io), 11 PB0/SD20/D0/CTS (io), 12 RUSB0 (io), 13 UDP0 (io), 14 UDM0 (io), 15 V33USB (power), 16 XO (io), 17 XI (in), 18 RUSB1 (io), 19 UDP1 (io), 20 UDM1 (io), 21 V33IO3 (power), 22 GND (power), 23 VCORE (power), 24 PB11/PWM6_/A14/CAP2_ (io), 25 PB12/A12 (io), 26 PB13/A13 (io), 27 PB8/RD#/RXD1_ (io), 28 PB9/TXD1_/WR# (io), 29 PB10/DBGIO/INT7 (io), 30 RST#/DBGCK (in), 31 PA3/PWM4/LED3/A3/CAP0/INT0 (io), 32 PA4/PWM0/LEDC/A4/RXD3/INT1 (io), 33 PA5/TXD3/PWM1/A5 (io), 34 PA6/SDCK/A6/RXD2/INT2 (io), 35 PA7/TXD2/CMD0/A7 (io), 36 PA8/PWM2/SD00/A8/RXD1 (io), 37 PA10/PWM5/SD02/A10/CAP1/INT3 (io), 38 PA11/PWM6/SD03/A11/CAP2/INT4 (io), 39 V33IO2 (power), 40 PA9/TXD1/PWM3/SD01/A9 (io), 41 V33REG (power), 42 GND (power), 43 VCORE (power), 44 PA15/MISO0/SD13/RXD0_ (io), 45 PA14/MOSI0/TXD0_/SD12 (io), 46 PA13/SCK0/SD11 (io), 47 PA12/SD10/SCS/INT5 (io), 48 PA2/MISO1/LED2/CMD3/A2 (io)

## CH567L_X
designator U?
32bit MCU with dual USB OTG 2.0 & quad SDIO & quad UART & AES
footprint LQFP48
pins: 1 PA1/MOSI1/LED1/CMD2/A1 (io), 2 PA0/SCK1/LED0/CMD1/A0 (io), 3 V33IO1 (power), 4 PB7/TXD0/SD33/D7 (io), 5 PB6/RTS/SD32/D6 (io), 6 PB5/DTR/SD31/D5 (io), 7 PB4/SD30/D4/RXD0/INT6 (io), 8 PB3/SD23/D3/DCD (io), 9 PB2/PWM5_/SD22/D2/CAP1_/RI (io), 10 PB1/SD21/D1/DSR (io), 11 PB0/SD20/D0/CTS (io), 12 RUSB0 (io), 13 UDP0 (io), 14 UDM0 (io), 15 V33USB (power), 16 XO (io), 17 XI (in), 18 RUSB1 (io), 19 UDP1 (io), 20 UDM1 (io), 21 V33IO3 (power), 22 GND (power), 23 VCORE (power), 24 PB11/PWM6_/A14/CAP2_ (io), 25 PB12/A12 (io), 26 PB13/A13 (io), 27 PB8/RD#/RXD1_ (io), 28 PB9/TXD1_/WR# (io), 29 PB10/DBGIO/INT7 (io), 30 RST#/DBGCK (in), 31 PA3/PWM4/LED3/A3/CAP0/INT0 (io), 32 PA4/PWM0/LEDC/A4/RXD3/INT1 (io), 33 PA5/TXD3/PWM1/A5 (io), 34 PA6/SDCK/A6/RXD2/INT2 (io), 35 PA7/TXD2/CMD0/A7 (io), 36 PA8/PWM2/SD00/A8/RXD1 (io), 37 PA10/PWM5/SD02/A10/CAP1/INT3 (io), 38 PA11/PWM6/SD03/A11/CAP2/INT4 (io), 39 V33IO2 (power), 40 PA9/TXD1/PWM3/SD01/A9 (io), 41 V33REG (power), 42 GND (power), 43 VCORE (power), 44 PA15/MISO0/SD13/RXD0_ (io), 45 PA14/MOSI0/TXD0_/SD12 (io), 46 PA13/SCK0/SD11 (io), 47 PA12/SD10/SCS/INT5 (io), 48 PA2/MISO1/LED2/CMD3/A2 (io)

## CH568L
designator U?
32bit MCU with USB OTG 2.0 & SATA G2 & quad SDIO & quad UART & AES
footprint LQFP48
pins: 1 GND (power), 2 VCC33 (power), 3 VCC12 (power), 4 SRXP (in), 5 SRXM (in), 6 VCC12A (power), 7 STXM (out), 8 STXP (out), 9 VCC12A (power), 10 RSATA (io), 11 PA15/MISO0/SD13/RXD0_ (io), 12 PA14/MOSI0/TXD0_/SD12 (io), 13 PA13/SCK0/SD11 (io), 14 PA12/SD10/SCS/INT5 (io), 15 PA2/MISO1/LED2/CMD3 (io), 16 PA1/MOSI1/LED1/CMD2 (io), 17 PA0/SCK1/LED0/CMD1 (io), 18 V33IO1 (power), 19 PB7/TXD0/SD33 (io), 20 PB6/RTS/SD32 (io), 21 PB5/DTR/SD31 (io), 22 PB4/SD30/RXD0/INT6 (io), 23 PB3/SD23/DCD (io), 24 PB2/PWM5_/SD22/CAP1_/RI (io), 25 PB1/SD21/DSR (io), 26 PB0/SD20/CTS (io), 27 VCC33 (power), 28 XO (io), 29 XI (in), 30 RUSB (io), 31 UD+ (io), 32 UD- (io), 33 V33IO3 (power), 34 GND (power), 35 VCC12 (power), 36 PB11/PWM6_/CAP2_ (io), 37 PB10/DBGIO/INT7 (io), 38 RST#/DBGCK (in), 39 PA3/PWM4/LED3/CAP0/INT0 (io), 40 PA4/PWM0/LEDC/RXD3/INT1 (io), 41 PA5/TXD3/PWM1 (io), 42 PA6/SDCK/RXD2/INT2 (io), 43 PA7/TXD2/CMD0 (io), 44 PA8/PWM2/SD00/RXD1 (io), 45 PA9/TXD1/PWM3/SD01 (io), 46 PA10/PWM5/SD02/CAP1/INT3 (io), 47 PA11/PWM6/SD03/CAP2/INT4 (io), 48 V33IO2 (power)

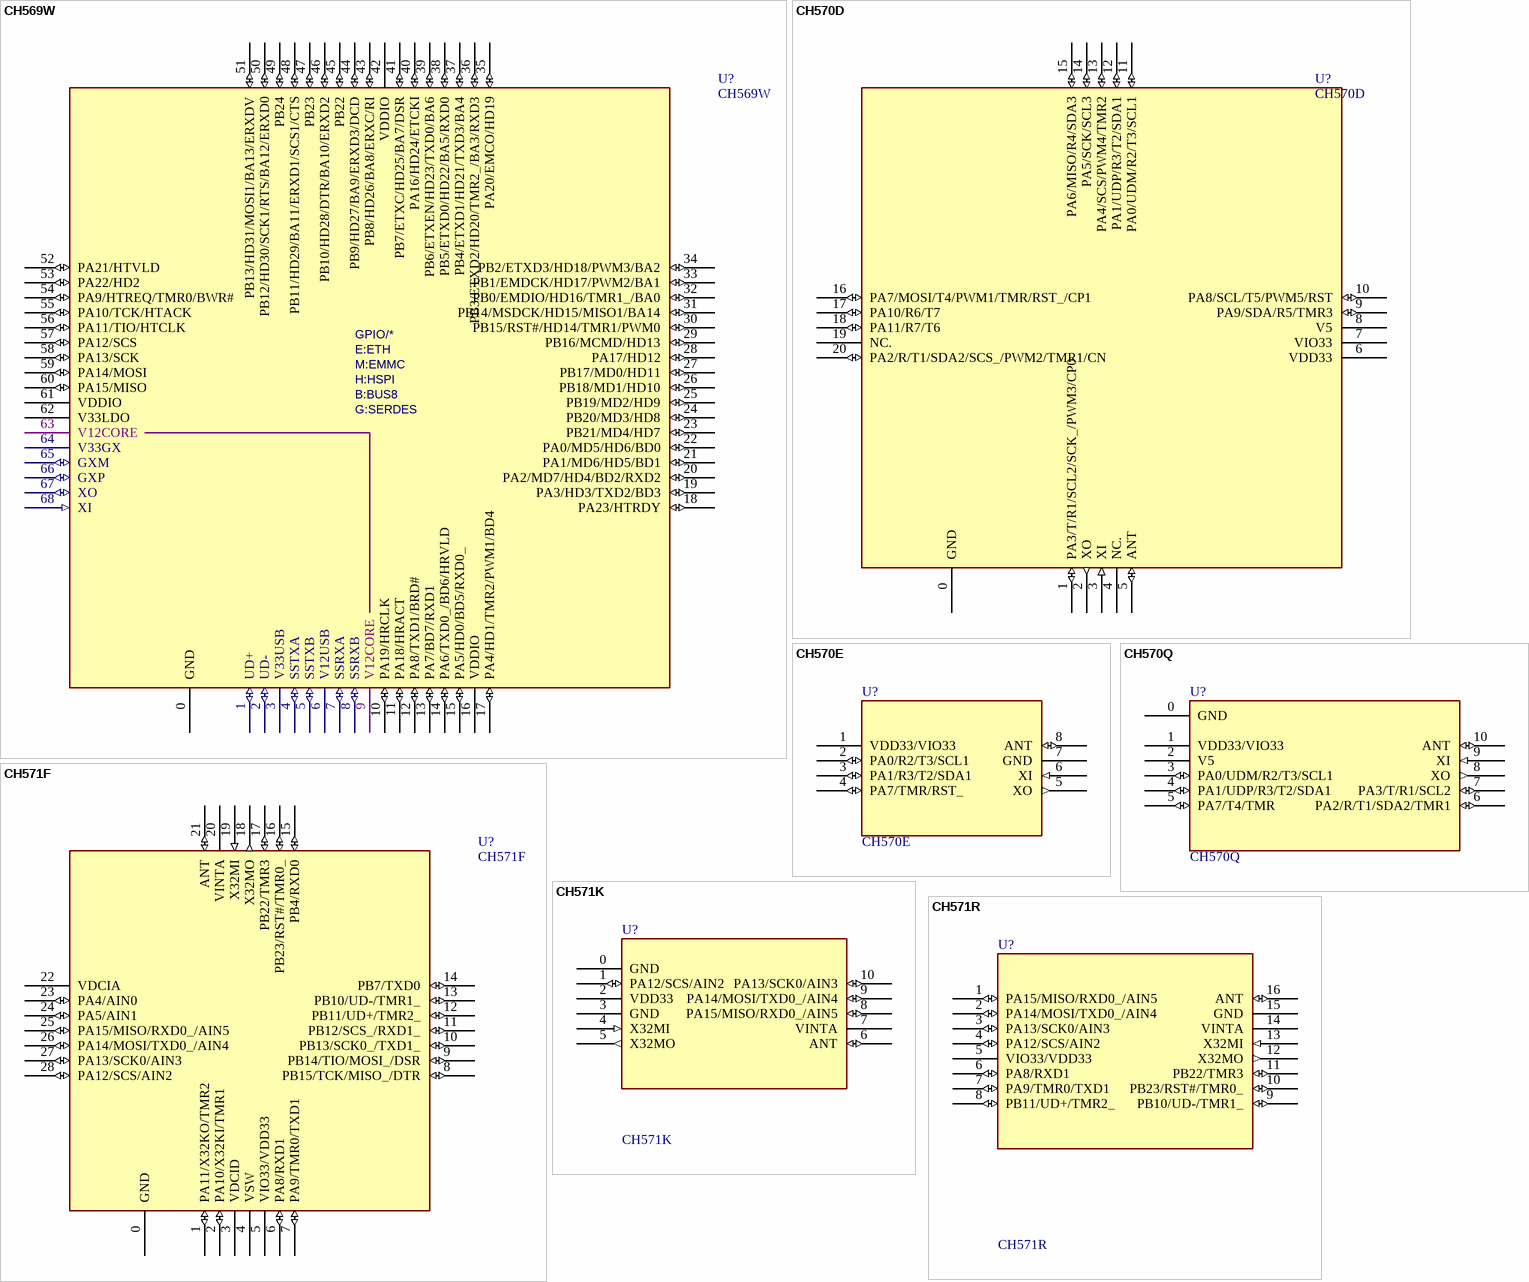
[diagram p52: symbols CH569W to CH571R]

## CH569W
designator U?
32bit RISC-V MCU with USB 3.0 SS/HS & 4*UART & ETH & HSPI
footprint QFN68_8X8
pins: 0 GND (power), 1 UD+ (io), 2 UD- (io), 3 V33USB (power), 4 SSTXA (io), 5 SSTXB (io), 6 V12USB (power), 7 SSRXA (io), 8 SSRXB (io), 9 V12CORE (power), 10 PA19/HRCLK (io), 11 PA18/HRACT (io), 12 PA8/TXD1/BRD# (io), 13 PA7/BD7/RXD1 (io), 14 PA6/TXD0_/BD6/HRVLD (io), 15 PA5/HD0/BD5/RXD0_ (io), 16 VDDIO (power), 17 PA4/HD1/TMR2/PWM1/BD4 (io), 18 PA23/HTRDY (io), 19 PA3/HD3/TXD2/BD3 (io), 20 PA2/MD7/HD4/BD2/RXD2 (io), 21 PA1/MD6/HD5/BD1 (io), 22 PA0/MD5/HD6/BD0 (io), 23 PB21/MD4/HD7 (io), 24 PB20/MD3/HD8 (io), 25 PB19/MD2/HD9 (io), 26 PB18/MD1/HD10 (io), 27 PB17/MD0/HD11 (io), 28 PA17/HD12 (io), 29 PB16/MCMD/HD13 (io), 30 PB15/RST#/HD14/TMR1/PWM0 (io), 31 PB14/MSDCK/HD15/MISO1/BA14 (io), 32 PB0/EMDIO/HD16/TMR1_/BA0 (io), 33 PB1/EMDCK/HD17/PWM2/BA1 (io), 34 PB2/ETXD3/HD18/PWM3/BA2 (io), 35 PA20/EMCO/HD19 (io), 36 PB3/ETXD2/HD20/TMR2_/BA3/RXD3 (io), 37 PB4/ETXD1/HD21/TXD3/BA4 (io), 38 PB5/ETXD0/HD22/BA5/RXD0 (io), 39 PB6/ETXEN/HD23/TXD0/BA6 (io), 40 PA16/HD24/ETCKI (io), 41 PB7/ETXC/HD25/BA7/DSR (io), 42 VDDIO (power), 43 PB8/HD26/BA8/ERXC/RI (io), 44 PB9/HD27/BA9/ERXD3/DCD (io), 45 PB22 (io), 46 PB10/HD28/DTR/BA10/ERXD2 (io), 47 PB23 (io), 48 PB11/HD29/BA11/ERXD1/SCS1/CTS (io), 49 PB24 (io), 50 PB12/HD30/SCK1/RTS/BA12/ERXD0 (io), 51 PB13/HD31/MOSI1/BA13/ERXDV (io), 52 PA21/HTVLD (io), 53 PA22/HD2 (io), 54 PA9/HTREQ/TMR0/BWR# (io), 55 PA10/TCK/HTACK (io), 56 PA11/TIO/HTCLK (io), 57 PA12/SCS (io), 58 PA13/SCK (io), 59 PA14/MOSI (io), 60 PA15/MISO (io), 61 VDDIO (power), 62 V33LDO (power), 63 V12CORE (power), 64 V33GX (power), 65 GXM (io), 66 GXP (io), 67 XO (io), 68 XI (in)

## CH570D
designator U?
RISC-V MCU with 2.4GHz Wireless/USB/SPI/UART/I2C/PWM/CMP
footprint QFN20_3X3 (Footprint not found)
pins: 0 GND (power), 1 PA3/T/R1/SCL2/SCK_/PWM3/CP0 (io), 2 XO (out), 3 XI (in), 4 NC., 5 ANT (io), 6 VDD33 (power), 7 VIO33 (power), 8 V5 (power), 9 PA9/SDA/R5/TMR3 (io), 10 PA8/SCL/T5/PWM5/RST (io), 11 PA0/UDM/R2/T3/SCL1 (io), 12 PA1/UDP/R3/T2/SDA1 (io), 13 PA4/SCS/PWM4/TMR2 (io), 14 PA5/SCK/SCL3 (io), 15 PA6/MISO/R4/SDA3 (io), 16 PA7/MOSI/T4/PWM1/TMR/RST_/CP1 (io), 17 PA10/R6/T7 (io), 18 PA11/R7/T6 (io), 19 NC., 20 PA2/R/T1/SDA2/SCS_/PWM2/TMR1/CN (io)

## CH570E
designator U?
RISC-V MCU with 2.4GHz Wireless/UART/I2C
footprint SOP8
pins: 1 VDD33/VIO33 (power), 2 PA0/R2/T3/SCL1 (io), 3 PA1/R3/T2/SDA1 (io), 4 PA7/TMR/RST_ (io), 5 XO (out), 6 XI (in), 7 GND (power), 8 ANT (io)

## CH570Q
designator U?
RISC-V MCU with 2.4GHz Wireless/USB/UART/I2C
footprint DFN10_3X3 (Footprint not found)
pins: 0 GND (power), 1 VDD33/VIO33 (power), 2 V5 (power), 3 PA0/UDM/R2/T3/SCL1 (io), 4 PA1/UDP/R3/T2/SDA1 (io), 5 PA7/T4/TMR (io), 6 PA2/R/T1/SDA2/TMR1 (io), 7 PA3/T/R1/SCL2 (io), 8 XO (out), 9 XI (in), 10 ANT (io)

## CH571F
designator U?
RISC-V MCU with BLE/USB/ADC/SPI/2*UART
footprint QFN28_4X4
pins: 0 GND (power), 1 PA11/X32KO/TMR2 (io), 2 PA10/X32KI/TMR1 (io), 3 VDCID (power), 4 VSW (power), 5 VIO33/VDD33 (power), 6 PA8/RXD1 (io), 7 PA9/TMR0/TXD1 (io), 8 PB15/TCK/MISO_/DTR (io), 9 PB14/TIO/MOSI_/DSR (io), 10 PB13/SCK0_/TXD1_ (io), 11 PB12/SCS_/RXD1_ (io), 12 PB11/UD+/TMR2_ (io), 13 PB10/UD-/TMR1_ (io), 14 PB7/TXD0 (io), 15 PB4/RXD0 (io), 16 PB23/RST#/TMR0_ (io), 17 PB22/TMR3 (io), 18 X32MO (out), 19 X32MI (in), 20 VINTA (power), 21 ANT (io), 22 VDCIA (power), 23 PA4/AIN0 (io), 24 PA5/AIN1 (io), 25 PA15/MISO/RXD0_/AIN5 (io), 26 PA14/MOSI/TXD0_/AIN4 (io), 27 PA13/SCK0/AIN3 (io), 28 PA12/SCS/AIN2 (io)

## CH571K
designator U?
RISC-V MCU with BLE/ADC/SPI/UART
footprint ESSOP10 (Footprint not found)
pins: 0 GND (power), 1 PA12/SCS/AIN2 (io), 2 VDD33 (power), 3 GND (power), 4 X32MI (in), 5 X32MO (out), 6 ANT (io), 7 VINTA (power), 8 PA15/MISO/RXD0_/AIN5 (io), 9 PA14/MOSI/TXD0_/AIN4 (io), 10 PA13/SCK0/AIN3 (io)

## CH571R
designator U?
RISC-V MCU with BLE/USB/ADC/SPI/2*UART
footprint TSSOP16 (Footprint not found)
pins: 1 PA15/MISO/RXD0_/AIN5 (io), 2 PA14/MOSI/TXD0_/AIN4 (io), 3 PA13/SCK0/AIN3 (io), 4 PA12/SCS/AIN2 (io), 5 VIO33/VDD33 (power), 6 PA8/RXD1 (io), 7 PA9/TMR0/TXD1 (io), 8 PB11/UD+/TMR2_ (io), 9 PB10/UD-/TMR1_ (io), 10 PB23/RST#/TMR0_ (io), 11 PB22/TMR3 (io), 12 X32MO (out), 13 X32MI (in), 14 VINTA (power), 15 GND (power), 16 ANT (io)

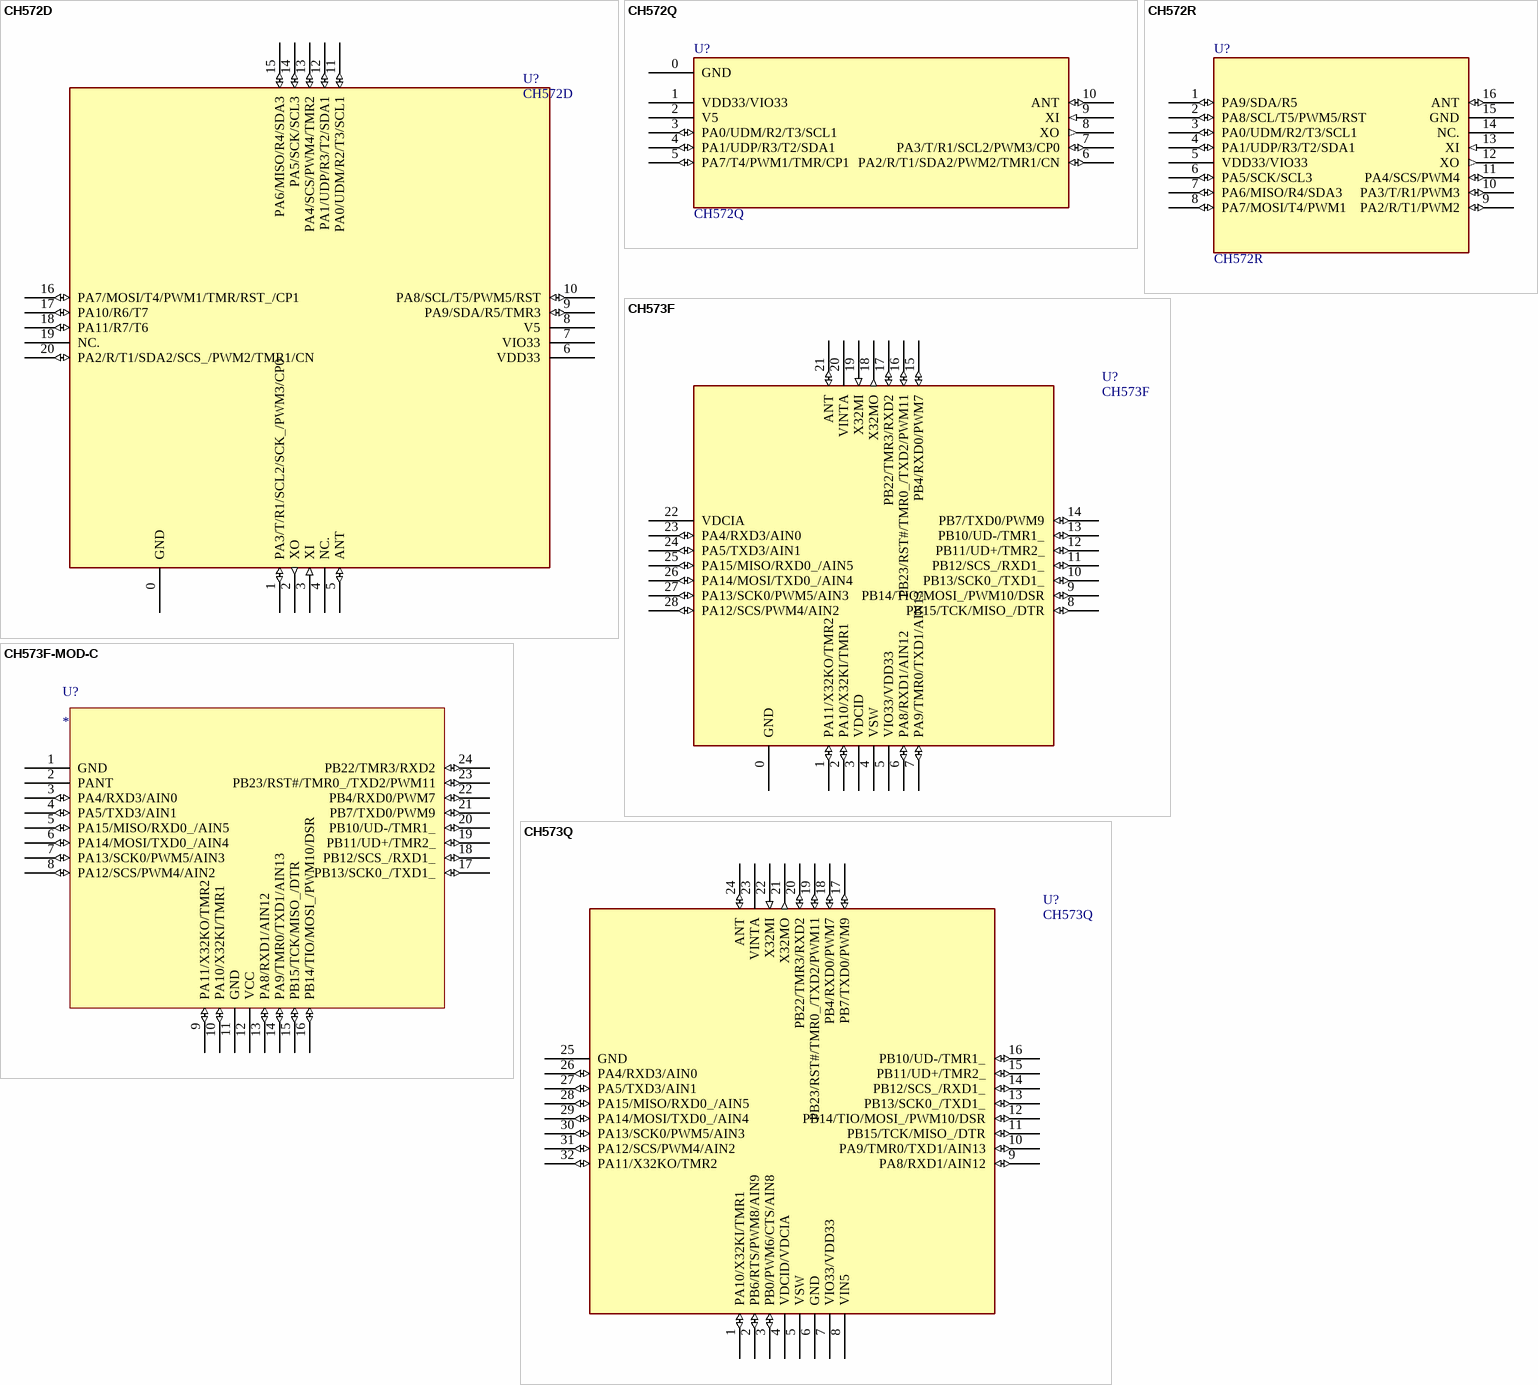
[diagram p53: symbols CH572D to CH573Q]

## CH572D
designator U?
RISC-V MCU with BLE/2.4GHz Wireless/USB/SPI/UART/I2C/PWM/CMP
footprint QFN20_3X3 (Footprint not found)
pins: 0 GND (power), 1 PA3/T/R1/SCL2/SCK_/PWM3/CP0 (io), 2 XO (out), 3 XI (in), 4 NC., 5 ANT (io), 6 VDD33 (power), 7 VIO33 (power), 8 V5 (power), 9 PA9/SDA/R5/TMR3 (io), 10 PA8/SCL/T5/PWM5/RST (io), 11 PA0/UDM/R2/T3/SCL1 (io), 12 PA1/UDP/R3/T2/SDA1 (io), 13 PA4/SCS/PWM4/TMR2 (io), 14 PA5/SCK/SCL3 (io), 15 PA6/MISO/R4/SDA3 (io), 16 PA7/MOSI/T4/PWM1/TMR/RST_/CP1 (io), 17 PA10/R6/T7 (io), 18 PA11/R7/T6 (io), 19 NC., 20 PA2/R/T1/SDA2/SCS_/PWM2/TMR1/CN (io)

## CH572Q
designator U?
RISC-V MCU with BLE/2.4GHz Wireless/USB/UART/I2C/PWM/CMP
footprint DFN10_3X3 (Footprint not found)
pins: 0 GND (power), 1 VDD33/VIO33 (power), 2 V5 (power), 3 PA0/UDM/R2/T3/SCL1 (io), 4 PA1/UDP/R3/T2/SDA1 (io), 5 PA7/T4/PWM1/TMR/CP1 (io), 6 PA2/R/T1/SDA2/PWM2/TMR1/CN (io), 7 PA3/T/R1/SCL2/PWM3/CP0 (io), 8 XO (out), 9 XI (in), 10 ANT (io)

## CH572R
designator U?
RISC-V MCU with BLE/2.4GHz Wireless/USB/SPI/UART/I2C/PWM/CMP
footprint TSSOP16
pins: 1 PA9/SDA/R5 (io), 2 PA8/SCL/T5/PWM5/RST (io), 3 PA0/UDM/R2/T3/SCL1 (io), 4 PA1/UDP/R3/T2/SDA1 (io), 5 VDD33/VIO33 (power), 6 PA5/SCK/SCL3 (io), 7 PA6/MISO/R4/SDA3 (io), 8 PA7/MOSI/T4/PWM1 (io), 9 PA2/R/T1/PWM2 (io), 10 PA3/T/R1/PWM3 (io), 11 PA4/SCS/PWM4 (io), 12 XO (out), 13 XI (in), 14 NC., 15 GND (power), 16 ANT (io)

## CH573F
designator U?
RISC-V MCU with BLE/USB/ADC/SPI/4*UART
footprint QFN28_4X4
pins: 0 GND (power), 1 PA11/X32KO/TMR2 (io), 2 PA10/X32KI/TMR1 (io), 3 VDCID (power), 4 VSW (power), 5 VIO33/VDD33 (power), 6 PA8/RXD1/AIN12 (io), 7 PA9/TMR0/TXD1/AIN13 (io), 8 PB15/TCK/MISO_/DTR (io), 9 PB14/TIO/MOSI_/PWM10/DSR (io), 10 PB13/SCK0_/TXD1_ (io), 11 PB12/SCS_/RXD1_ (io), 12 PB11/UD+/TMR2_ (io), 13 PB10/UD-/TMR1_ (io), 14 PB7/TXD0/PWM9 (io), 15 PB4/RXD0/PWM7 (io), 16 PB23/RST#/TMR0_/TXD2/PWM11 (io), 17 PB22/TMR3/RXD2 (io), 18 X32MO (out), 19 X32MI (in), 20 VINTA (power), 21 ANT (io), 22 VDCIA (power), 23 PA4/RXD3/AIN0 (io), 24 PA5/TXD3/AIN1 (io), 25 PA15/MISO/RXD0_/AIN5 (io), 26 PA14/MOSI/TXD0_/AIN4 (io), 27 PA13/SCK0/PWM5/AIN3 (io), 28 PA12/SCS/PWM4/AIN2 (io)

## CH573F-MOD-C
designator U?
CH573F module, RISC-V MCU with BLE/USB/ADC/SPI/4*UART
footprint BLEMOD-R2-1v0-24PIN
pins: 1 GND (power), 2 PANT, 3 PA4/RXD3/AIN0  (io), 4 PA5/TXD3/AIN1   (io), 5 PA15/MISO/RXD0_/AIN5   (io), 6 PA14/MOSI/TXD0_/AIN4 (io), 7 PA13/SCK0/PWM5/AIN3   (io), 8 PA12/SCS/PWM4/AIN2   (io), 9 PA11/X32KO/TMR2   (io), 10 PA10/X32KI/TMR1   (io), 11 GND (power), 12 VCC (power), 13 PA8/RXD1/AIN12   (io), 14 PA9/TMR0/TXD1/AIN13  (io), 15 PB15/TCK/MISO_/DTR (io), 16 PB14/TIO/MOSI_/PWM10/DSR (io), 17 PB13/SCK0_/TXD1_ (io), 18 PB12/SCS_/RXD1_ (io), 19 PB11/UD+/TMR2_ (io), 20 PB10/UD-/TMR1_ (io), 21 PB7/TXD0/PWM9 (io), 22 PB4/RXD0/PWM7 (io), 23 PB23/RST#/TMR0_/TXD2/PWM11 (io), 24 PB22/TMR3/RXD2 (io)

## CH573Q
designator U?
RISC-V MCU with BLE/USB/ADC/SPI/4*UART
footprint LQFP32 (Footprint not found)
pins: 1 PA10/X32KI/TMR1 (io), 2 PB6/RTS/PWM8/AIN9 (io), 3 PB0/PWM6/CTS/AIN8 (io), 4 VDCID/VDCIA (power), 5 VSW (power), 6 GND (power), 7 VIO33/VDD33 (power), 8 VIN5 (power), 9 PA8/RXD1/AIN12 (io), 10 PA9/TMR0/TXD1/AIN13 (io), 11 PB15/TCK/MISO_/DTR (io), 12 PB14/TIO/MOSI_/PWM10/DSR (io), 13 PB13/SCK0_/TXD1_ (io), 14 PB12/SCS_/RXD1_ (io), 15 PB11/UD+/TMR2_ (io), 16 PB10/UD-/TMR1_ (io), 17 PB7/TXD0/PWM9 (io), 18 PB4/RXD0/PWM7 (io), 19 PB23/RST#/TMR0_/TXD2/PWM11 (io), 20 PB22/TMR3/RXD2 (io), 21 X32MO (out), 22 X32MI (in), 23 VINTA (power), 24 ANT (io), 25 GND (power), 26 PA4/RXD3/AIN0 (io), 27 PA5/TXD3/AIN1 (io), 28 PA15/MISO/RXD0_/AIN5 (io), 29 PA14/MOSI/TXD0_/AIN4 (io), 30 PA13/SCK0/PWM5/AIN3 (io), 31 PA12/SCS/PWM4/AIN2 (io), 32 PA11/X32KO/TMR2 (io)

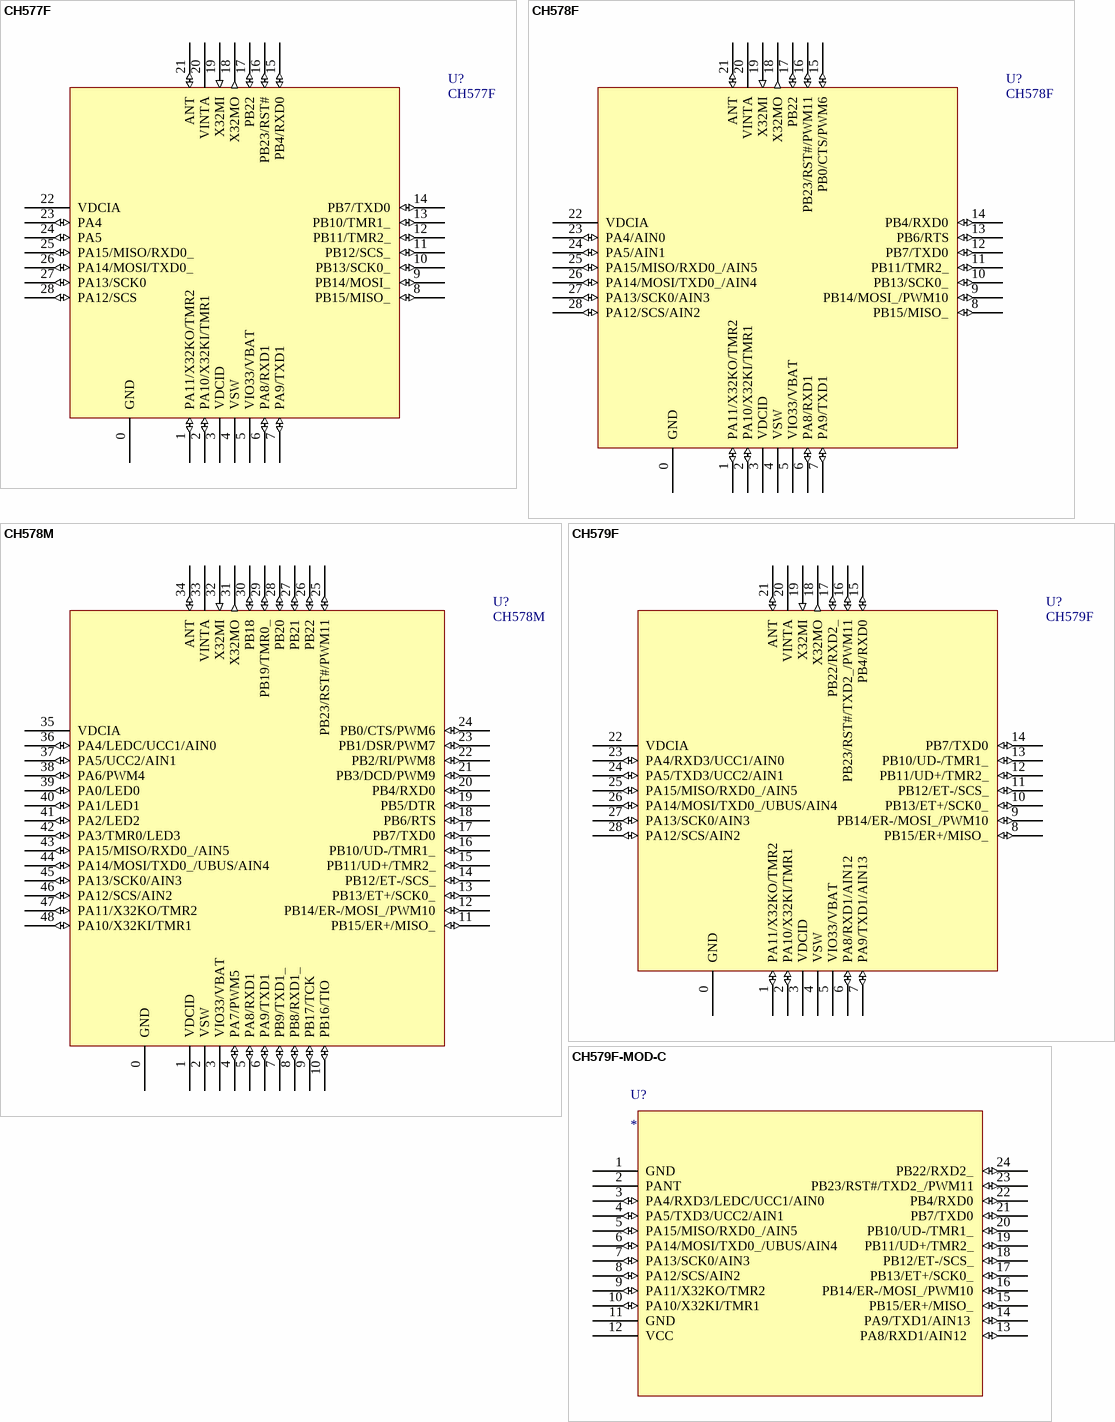
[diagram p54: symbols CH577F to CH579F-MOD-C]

## CH577F
designator U?
ARM M0 MCU with Bluetooth-LowEnergy+doubleUART+SPI
footprint QFN28_4X4
pins: 0 GND (power), 1 PA11/X32KO/TMR2 (io), 2 PA10/X32KI/TMR1 (io), 3 VDCID (power), 4 VSW (power), 5 VIO33/VBAT (power), 6 PA8/RXD1 (io), 7 PA9/TXD1 (io), 8 PB15/MISO_ (io), 9 PB14/MOSI_ (io), 10 PB13/SCK0_ (io), 11 PB12/SCS_ (io), 12 PB11/TMR2_ (io), 13 PB10/TMR1_ (io), 14 PB7/TXD0 (io), 15 PB4/RXD0 (io), 16 PB23/RST# (io), 17 PB22 (io), 18 X32MO (out), 19 X32MI (in), 20 VINTA (power), 21 ANT (io), 22 VDCIA (power), 23 PA4 (io), 24 PA5 (io), 25 PA15/MISO/RXD0_ (io), 26 PA14/MOSI/TXD0_ (io), 27 PA13/SCK0 (io), 28 PA12/SCS (io)

## CH578F
designator U?
ARM M0 MCU with Bluetooth-LowEnergy+doubleUART+SPI+ADC
footprint QFN28_4X4
pins: 0 GND (power), 1 PA11/X32KO/TMR2 (io), 2 PA10/X32KI/TMR1 (io), 3 VDCID (power), 4 VSW (power), 5 VIO33/VBAT (power), 6 PA8/RXD1 (io), 7 PA9/TXD1 (io), 8 PB15/MISO_ (io), 9 PB14/MOSI_/PWM10 (io), 10 PB13/SCK0_ (io), 11 PB11/TMR2_ (io), 12 PB7/TXD0 (io), 13 PB6/RTS (io), 14 PB4/RXD0 (io), 15 PB0/CTS/PWM6 (io), 16 PB23/RST#/PWM11 (io), 17 PB22 (io), 18 X32MO (out), 19 X32MI (in), 20 VINTA (power), 21 ANT (io), 22 VDCIA (power), 23 PA4/AIN0 (io), 24 PA5/AIN1 (io), 25 PA15/MISO/RXD0_/AIN5 (io), 26 PA14/MOSI/TXD0_/AIN4 (io), 27 PA13/SCK0/AIN3 (io), 28 PA12/SCS/AIN2 (io)

## CH578M
designator U?
ARM M0 MCU with Bluetooth-LowEnergy+Ethernet+USB+segment-LCD
footprint QFN48_5X5
pins: 0 GND (power), 1 VDCID (power), 2 VSW (power), 3 VIO33/VBAT (power), 4 PA7/PWM5 (io), 5 PA8/RXD1 (io), 6 PA9/TXD1 (io), 7 PB9/TXD1_ (io), 8 PB8/RXD1_ (io), 9 PB17/TCK (io), 10 PB16/TIO (io), 11 PB15/ER+/MISO_ (io), 12 PB14/ER-/MOSI_/PWM10 (io), 13 PB13/ET+/SCK0_ (io), 14 PB12/ET-/SCS_ (io), 15 PB11/UD+/TMR2_ (io), 16 PB10/UD-/TMR1_ (io), 17 PB7/TXD0 (io), 18 PB6/RTS (io), 19 PB5/DTR (io), 20 PB4/RXD0 (io), 21 PB3/DCD/PWM9 (io), 22 PB2/RI/PWM8 (io), 23 PB1/DSR/PWM7 (io), 24 PB0/CTS/PWM6 (io), 25 PB23/RST#/PWM11 (io), 26 PB22 (io), 27 PB21 (io), 28 PB20 (io), 29 PB19/TMR0_ (io), 30 PB18 (io), 31 X32MO (out), 32 X32MI (in), 33 VINTA (power), 34 ANT (io), 35 VDCIA (power), 36 PA4/LEDC/UCC1/AIN0 (io), 37 PA5/UCC2/AIN1 (io), 38 PA6/PWM4 (io), 39 PA0/LED0 (io), 40 PA1/LED1 (io), 41 PA2/LED2 (io), 42 PA3/TMR0/LED3 (io), 43 PA15/MISO/RXD0_/AIN5 (io), 44 PA14/MOSI/TXD0_/UBUS/AIN4 (io), 45 PA13/SCK0/AIN3 (io), 46 PA12/SCS/AIN2 (io), 47 PA11/X32KO/TMR2 (io), 48 PA10/X32KI/TMR1 (io)

## CH579F
designator U?
ARM M0 MCU with Bluetooth-LowEnergy+Ethernet+USB Host/Device
footprint QFN28_4X4
pins: 0 GND (power), 1 PA11/X32KO/TMR2 (io), 2 PA10/X32KI/TMR1 (io), 3 VDCID (power), 4 VSW (power), 5 VIO33/VBAT (power), 6 PA8/RXD1/AIN12 (io), 7 PA9/TXD1/AIN13 (io), 8 PB15/ER+/MISO_ (io), 9 PB14/ER-/MOSI_/PWM10 (io), 10 PB13/ET+/SCK0_ (io), 11 PB12/ET-/SCS_ (io), 12 PB11/UD+/TMR2_ (io), 13 PB10/UD-/TMR1_ (io), 14 PB7/TXD0 (io), 15 PB4/RXD0 (io), 16 PB23/RST#/TXD2_/PWM11 (io), 17 PB22/RXD2_ (io), 18 X32MO (out), 19 X32MI (in), 20 VINTA (power), 21 ANT (io), 22 VDCIA (power), 23 PA4/RXD3/UCC1/AIN0 (io), 24 PA5/TXD3/UCC2/AIN1 (io), 25 PA15/MISO/RXD0_/AIN5 (io), 26 PA14/MOSI/TXD0_/UBUS/AIN4 (io), 27 PA13/SCK0/AIN3 (io), 28 PA12/SCS/AIN2 (io)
